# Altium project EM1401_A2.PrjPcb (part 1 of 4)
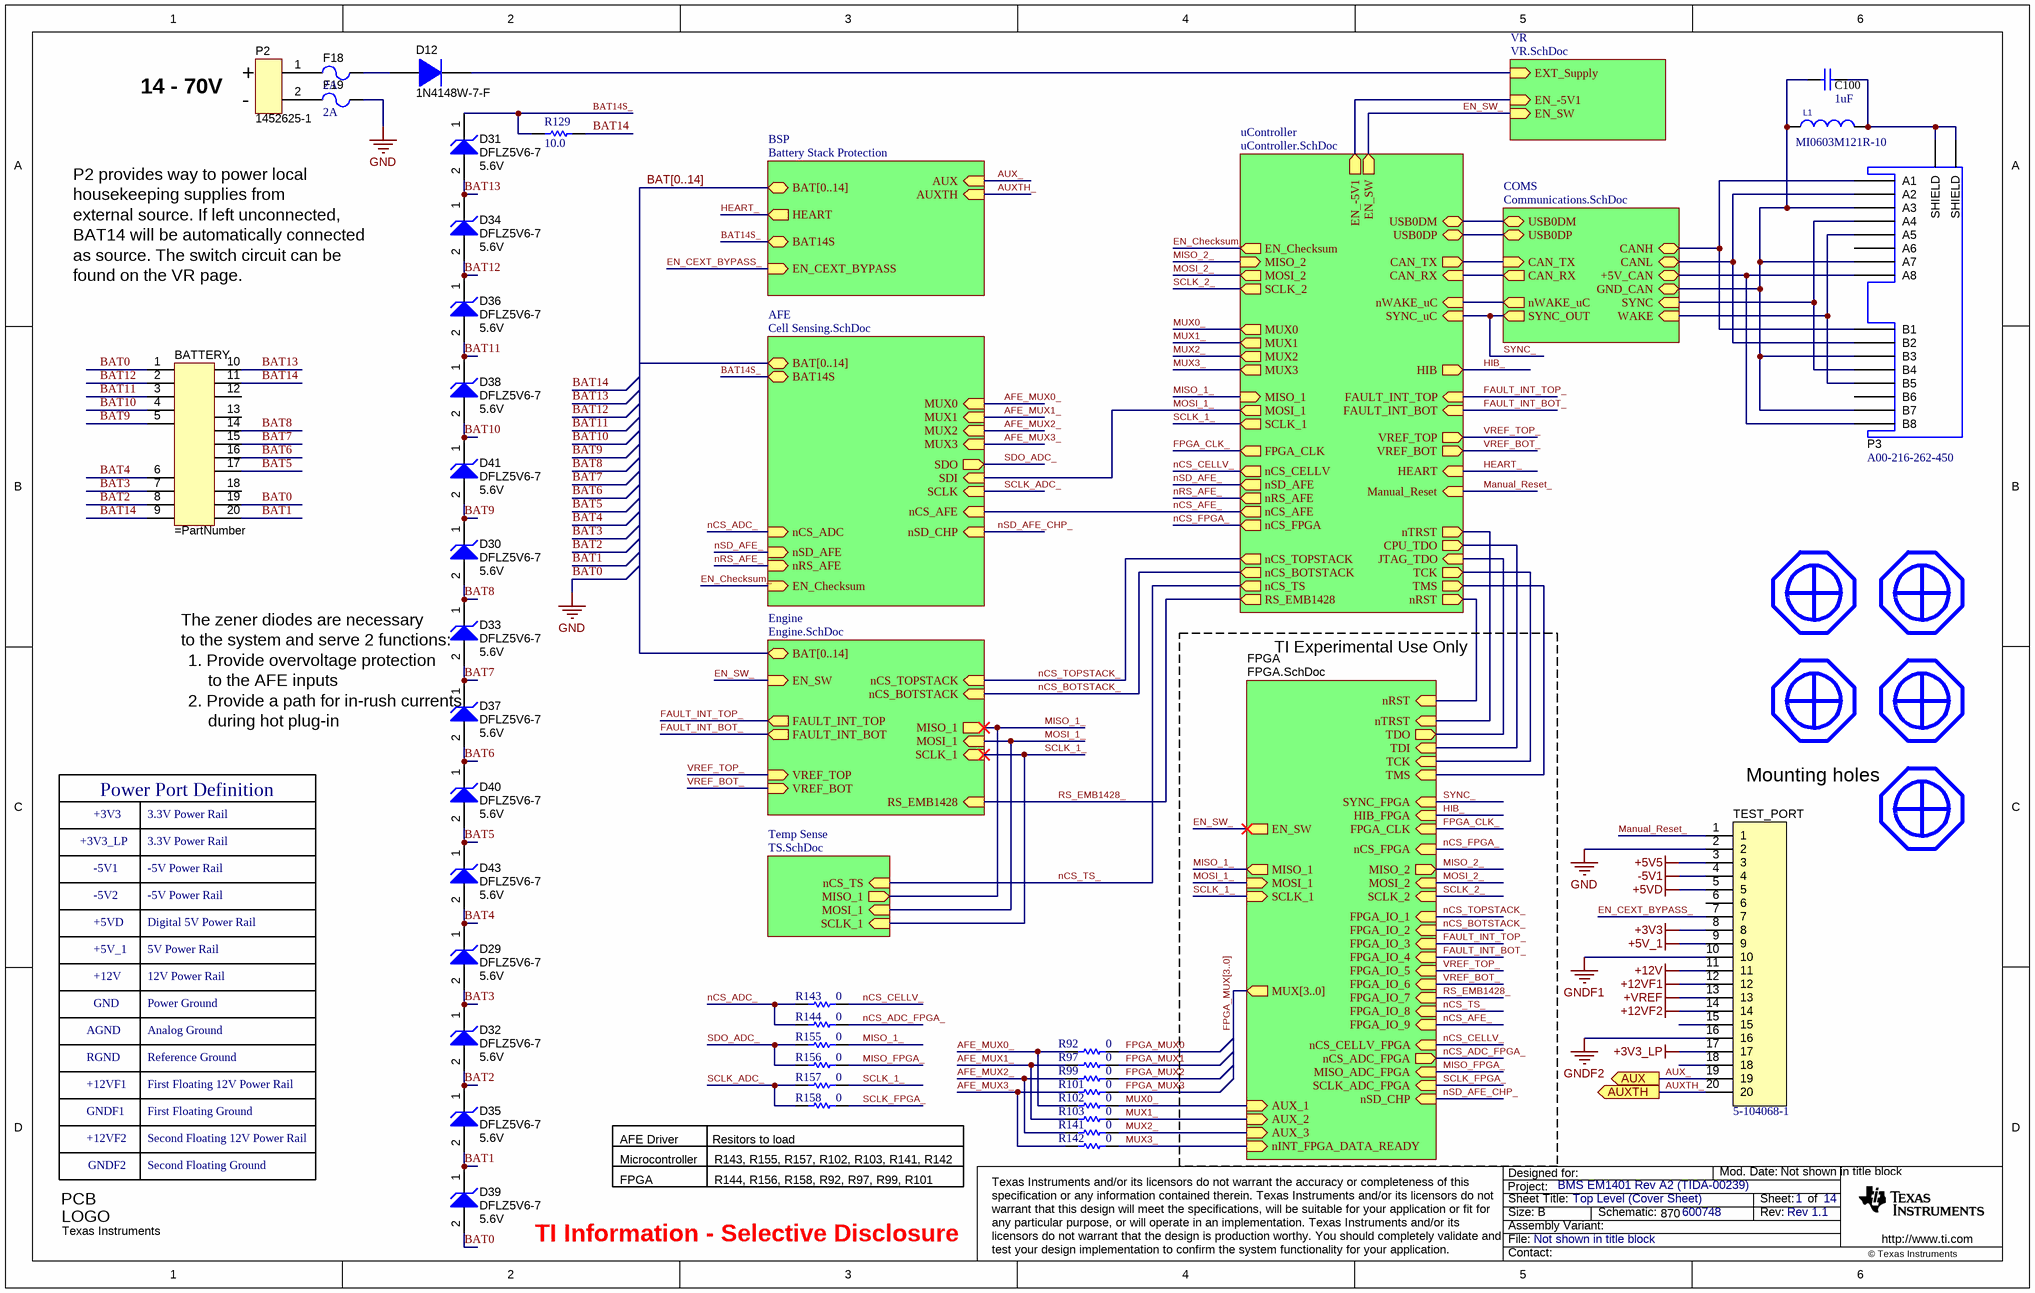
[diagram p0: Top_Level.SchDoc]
SCH_Rev: Rev 1.1; PRJ_Title: BMS EM1401 Rev A2 (TIDA-00239); PRJ_BasePN: 600748; PCB_MinorRev: A2
14 sheets, 751 parts. Net scope: hierarchical (ports join the sheet entries above them; power ports are global).
Board file: EM1401_RevA2.PcbDoc
Sheets:
  Top_Level.SchDoc
    Engine = Engine.SchDoc
      Top Half Stack = TOP Half Stack.SchDoc
        TOP_Converter = TOP_ACB_Converter.SchDoc
      Bottom Half Stack = BOTTOM Half Stack.SchDoc
        BOTTOM_Converter = BOTTOM_ACB_Converter.SchDoc
    VR = VR.SchDoc
    AFE = Cell Sensing.SchDoc
    uController = uController.SchDoc
    COMS = Communications.SchDoc
    BSP = Battery Stack Protection.SchDoc
    Temp Sense = TS.SchDoc
    FPGA = FPGA.SchDoc
  Revision_History.SchDoc

## Sheet Top_Level.SchDoc: Top Level (Cover Sheet)
size B; Date: Not shown in title block; ApprovedBy: Not shown in title block; CheckedBy: Not shown in title block; Author: Not shown in title block; CompanyName: Not shown in title block; DrawnBy: Not shown in title block; Engineer: Not shown in title block; Organization: Not shown in title block; Address1: Not shown in title block; Address2: Not shown in title block; Address3: Not shown in title block; Address4: Not shown in title block; DocumentNumber: 1; Revision: Use project parameter SCH_Rev; SheetNumber: 1; SheetTotal: 14; PageSetup: Record=PageOptions|CenterHorizontal=True|CenterVertical=True|PrintScale=1.09|XCorrection=1.00|YCorrection=1.00|PrintKind=0|BorderSize=5000000|LeftOffset=0|BottomOffset=0|Orientation=2|PaperLength=1000|PaperWidth=1000|Scale=100|PaperSource=15|PrintQuality=600|MediaType=1|DitherType=10|PaperKind=11x17|PrintScaleMode=1

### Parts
BATTERY  (no value)  [175785]
C100  value 1uF  [0805_HV]  (hidden comment: C2012X7R1E105K)
D12  1N4148W-7-F  [SOD-123]
D29  DFLZ5V6-7  value 5.6V  [powerDI123]
D30  DFLZ5V6-7  value 5.6V  [powerDI123]
D31  DFLZ5V6-7  value 5.6V  [powerDI123]
D32  DFLZ5V6-7  value 5.6V  [powerDI123]
D33  DFLZ5V6-7  value 5.6V  [powerDI123]
D34  DFLZ5V6-7  value 5.6V  [powerDI123]
D35  DFLZ5V6-7  value 5.6V  [powerDI123]
D36  DFLZ5V6-7  value 5.6V  [powerDI123]
D37  DFLZ5V6-7  value 5.6V  [powerDI123]
D38  DFLZ5V6-7  value 5.6V  [powerDI123]
D39  DFLZ5V6-7  value 5.6V  [powerDI123]
D40  DFLZ5V6-7  value 5.6V  [powerDI123]
D41  DFLZ5V6-7  value 5.6V  [powerDI123]
D43  DFLZ5V6-7  value 5.6V  [powerDI123]
F18  value 2A  [0459002.UR]  (hidden comment: 0459002.UR)
F19  value 2A  [0459002.UR]  (hidden comment: 0459002.UR)
L1  MI0603M121R-10  [0603]
Logo1  Texas Instruments  [TI_Logo_CopperSolderMask_1p1_x_p275]  (no BOM)
MNT1  Used in BOM report  [4-40 screw]  (value not drawn)
MNT2  Used in BOM report  [4-40 screw]  (value not drawn)
MNT3  Used in BOM report  [4-40 screw]  (value not drawn)
MNT4  Used in BOM report  [4-40 screw]  (value not drawn)
MNT5  Used in BOM report  [4-40 screw]  (value not drawn)
P2  1452625-1  [1452625-1]
P3  A00-216-262-450  [A00-216-262-450]
R92  value 0  [0603L]  (hidden comment: CRCW06030000Z0EA)
R97  value 0  [0603L]  (hidden comment: CRCW06030000Z0EA)
R99  value 0  [0603L]  (hidden comment: CRCW06030000Z0EA)
R101  value 0  [0603L]  (hidden comment: CRCW06030000Z0EA)
R102  value 0  [0603L]  (hidden comment: CRCW06030000Z0EA)
R103  value 0  [0603L]  (hidden comment: CRCW06030000Z0EA)
R129  value 10.0  [0805_HV]  (hidden comment: CRCW080510R0FKEA)
R141  value 0  [0603L]  (hidden comment: CRCW06030000Z0EA)
R142  value 0  [0603L]  (hidden comment: CRCW06030000Z0EA)
R143  value 0  [0603L]  (hidden comment: CRCW06030000Z0EA)
R144  value 0  [0603L]  (hidden comment: CRCW06030000Z0EA)
R155  value 0  [0603L]  (hidden comment: CRCW06030000Z0EA)
R156  value 0  [0603L]  (hidden comment: CRCW06030000Z0EA)
R157  value 0  [0603L]  (hidden comment: CRCW06030000Z0EA)
R158  value 0  [0603L]  (hidden comment: CRCW06030000Z0EA)
TEST_PORT  5-104068-1  [5-104068-1]

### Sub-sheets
AFE = Cell Sensing.SchDoc: BAT[0..14], nCS_AFE (in), MUX0 (in), MUX1 (in), MUX2 (in), MUX3 (in), BAT14S, SDI (in), SCLK (in), nSD_AFE (in), nRS_AFE (in), nCS_ADC (in), EN_Checksum (in), SDO (out), nSD_CHP (in)
BSP = Battery Stack Protection: HEART (out), BAT[0..14], BAT14S, EN_CEXT_BYPASS (in), AUXTH (in), AUX (in)
COMS = Communications.SchDoc: CAN_TX (in), CAN_RX (out), +5V_CAN, CANL, CANH, nWAKE_uC (out), SYNC_OUT (out), SYNC (in), WAKE (in), GND_CAN, USB0DM (bidir), USB0DP (bidir)
Engine = Engine.SchDoc: MOSI_1 (in), MISO_1 (out), BAT[0..14], SCLK_1 (in), nCS_TOPSTACK (in), nCS_BOTSTACK (in), VREF_BOT (in), VREF_TOP (in), FAULT_INT_TOP (out), FAULT_INT_BOT (out), RS_EMB1428 (in), EN_SW (in)
FPGA = FPGA.SchDoc: TDO (out), TDI (in), TCK (in), TMS (in), nTRST (in), nCS_FPGA (in), nRST (in), SYNC_FPGA (in), SCLK_2 (in), MISO_2 (out), MOSI_2 (in), HIB_FPGA (in), FPGA_CLK (in), FPGA_IO_1 (in), FPGA_IO_2 (in), FPGA_IO_3 (in), FPGA_IO_4 (in), FPGA_IO_5 (in), FPGA_IO_6 (in), FPGA_IO_7 (in), FPGA_IO_8 (in), FPGA_IO_9 (in), MUX[3..0] (out), AUX_2 (in), AUX_1 (in), AUX_3 (in), nINT_FPGA_DATA_READY (in), nCS_CELLV_FPGA (in), nCS_ADC_FPGA (out), MISO_ADC_FPGA (in), SCLK_ADC_FPGA (in), SCLK_1 (in), MISO_1 (out), MOSI_1 (in), nSD_CHP (in), EN_SW (out)
Temp Sense = TS.SchDoc: nCS_TS (in), MOSI_1 (in), MISO_1 (out), SCLK_1 (in)
uController = uController.SchDoc: CAN_TX (out), CAN_RX (in), SCLK_1 (out), MOSI_1 (out), MUX0 (out), MUX1 (out), MUX2 (out), MUX3 (out), nSD_AFE (out), nRS_AFE (out), MISO_1 (in), nCS_TOPSTACK (out), nCS_BOTSTACK (out), nCS_AFE (out), nCS_TS (out), EN_-5V1 (out), EN_SW (out), VREF_TOP (out), VREF_BOT (out), nCS_CELLV (out), HEART (in), RS_EMB1428 (out), nWAKE_uC (in), SCLK_2 (out), MISO_2 (in), MOSI_2 (out), EN_Checksum (out), SYNC_uC (in), USB0DM (bidir), USB0DP (bidir), Manual_Reset (in), JTAG_TDO (in), TCK (out), TMS (out), nRST (out), nTRST (out), FAULT_INT_BOT (in), FAULT_INT_TOP (in), HIB (out), FPGA_CLK (out), nCS_FPGA (out), CPU_TDO (out)
VR = VR.SchDoc: EN_-5V1 (in), EN_SW (in), EXT_Supply (in)

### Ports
AUX (out), AUXTH (out)

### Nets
+3V3: TEST_PORT.8
+3V3_LP: TEST_PORT.17
+5V5: TEST_PORT.3
+5V_1: TEST_PORT.9
+5V_CAN: P3.A8 P3.B8 ; sheet COMS/+5V_CAN
+5VD: TEST_PORT.5
+12V: TEST_PORT.11
+12VF1: TEST_PORT.12
+12VF2: TEST_PORT.14
+VREF: TEST_PORT.13
-5V1: TEST_PORT.4
BAT0: BATTERY.1 BATTERY.19 D39.2(A) F19.1 TEST_PORT.2  [also labelled GND]
CAN_GND: C100.1 L1.1 P3.A3 P3.A7 P3.B3 P3.B7 ; sheet COMS/GND_CAN
GNDF1: TEST_PORT.10
GNDF2: TEST_PORT.16
AFE_MUX0_: R92.2 R102.2 ; sheet AFE/MUX0
AFE_MUX1_: R97.2 R103.2 ; sheet AFE/MUX1
AFE_MUX2_: R99.2 R141.2 ; sheet AFE/MUX2
AFE_MUX3_: R101.2 R142.2 ; sheet AFE/MUX3
AUX_: TEST_PORT.19 ; port AUX, sheet BSP/AUX
AUXTH_: TEST_PORT.20 ; port AUXTH, sheet BSP/AUXTH
BAT1: BATTERY.20 D35.2(A) D39.1(K)
BAT2: BATTERY.8 D32.2(A) D35.1(K)
BAT3: BATTERY.7 D29.2(A) D32.1(K)
BAT4: BATTERY.6 D29.1(K) D43.2(A)
BAT5: BATTERY.17 D40.2(A) D43.1(K)
BAT6: BATTERY.16 D37.2(A) D40.1(K)
BAT7: BATTERY.15 D33.2(A) D37.1(K)
BAT8: BATTERY.14 D30.2(A) D33.1(K)
BAT9: BATTERY.5 D30.1(K) D41.2(A)
BAT10: BATTERY.4 D38.2(A) D41.1(K)
BAT11: BATTERY.3 D36.2(A) D38.1(K)
BAT12: BATTERY.2 D34.2(A) D36.1(K)
BAT13: BATTERY.10 D31.2(A) D34.1(K)
BAT14: BATTERY.9 BATTERY.11 R129.1
BAT14S_: D31.1(K) R129.2 ; sheet AFE/BAT14S, sheet BSP/BAT14S
EN_CEXT_BYPASS_: TEST_PORT.7 ; sheet BSP/EN_CEXT_BYPASS
EN_Checksum_: sheet AFE/EN_Checksum, sheet uController/EN_Checksum
EN_SW_: sheet Engine/EN_SW, sheet VR/EN_SW, sheet uController/EN_SW, sheet FPGA/EN_SW
FAULT_INT_BOT_: sheet Engine/FAULT_INT_BOT, sheet uController/FAULT_INT_BOT, sheet FPGA/FPGA_IO_4
FAULT_INT_TOP_: sheet Engine/FAULT_INT_TOP, sheet uController/FAULT_INT_TOP, sheet FPGA/FPGA_IO_3
FPGA_CLK_: sheet uController/FPGA_CLK, sheet FPGA/FPGA_CLK
FPGA_MUX0: R92.1
FPGA_MUX1: R97.1
FPGA_MUX2: R99.1
FPGA_MUX3: R101.1
HEART_: sheet uController/HEART, sheet BSP/HEART
HIB_: sheet uController/HIB, sheet FPGA/HIB_FPGA
JTAG_TDO: sheet uController/JTAG_TDO, sheet FPGA/TDO
JTCK/SWCLK: sheet uController/TCK, sheet FPGA/TCK
JTDO/TRACESWO: sheet uController/CPU_TDO, sheet FPGA/TDI
JTMS/SWDIO: sheet uController/TMS, sheet FPGA/TMS
Manual_Reset_: TEST_PORT.1 ; sheet uController/Manual_Reset
MISO_1_: R155.2 ; sheet Engine/MISO_1, sheet uController/MISO_1, sheet Temp Sense/MISO_1, sheet FPGA/MISO_1
MISO_2_: sheet uController/MISO_2, sheet FPGA/MISO_2
MISO_FPGA_: R156.2 ; sheet FPGA/MISO_ADC_FPGA
MOSI_1_: sheet Engine/MOSI_1, sheet AFE/SDI, sheet uController/MOSI_1, sheet Temp Sense/MOSI_1, sheet FPGA/MOSI_1
MOSI_2_: sheet uController/MOSI_2, sheet FPGA/MOSI_2
MUX0_: R102.1 ; sheet uController/MUX0, sheet FPGA/AUX_1
MUX1_: R103.1 ; sheet uController/MUX1, sheet FPGA/AUX_2
MUX2_: R141.1 ; sheet uController/MUX2, sheet FPGA/AUX_3
MUX3_: R142.1 ; sheet uController/MUX3, sheet FPGA/nINT_FPGA_DATA_READY
nCS_ADC_: R143.2 R144.2 ; sheet AFE/nCS_ADC
nCS_ADC_FPGA_: R144.1 ; sheet FPGA/nCS_ADC_FPGA
nCS_AFE_: sheet AFE/nCS_AFE, sheet uController/nCS_AFE, sheet FPGA/FPGA_IO_9
nCS_BOTSTACK_: sheet Engine/nCS_BOTSTACK, sheet uController/nCS_BOTSTACK, sheet FPGA/FPGA_IO_2
nCS_CELLV_: R143.1 ; sheet uController/nCS_CELLV, sheet FPGA/nCS_CELLV_FPGA
nCS_FPGA_: sheet uController/nCS_FPGA, sheet FPGA/nCS_FPGA
nCS_TOPSTACK_: sheet Engine/nCS_TOPSTACK, sheet uController/nCS_TOPSTACK, sheet FPGA/FPGA_IO_1
nCS_TS_: sheet uController/nCS_TS, sheet Temp Sense/nCS_TS, sheet FPGA/FPGA_IO_8
nRS_AFE_: sheet AFE/nRS_AFE, sheet uController/nRS_AFE
nRST: sheet uController/nRST, sheet FPGA/nRST
nSD_AFE_: sheet AFE/nSD_AFE, sheet uController/nSD_AFE
nSD_AFE_CHP_: sheet AFE/nSD_CHP, sheet FPGA/nSD_CHP
RS_EMB1428_: sheet Engine/RS_EMB1428, sheet uController/RS_EMB1428, sheet FPGA/FPGA_IO_7
SCLK_1_: R157.2 ; sheet Engine/SCLK_1, sheet uController/SCLK_1, sheet Temp Sense/SCLK_1, sheet FPGA/SCLK_1
SCLK_2_: sheet uController/SCLK_2, sheet FPGA/SCLK_2
SCLK_ADC_: R157.1 R158.1 ; sheet AFE/SCLK
SCLK_FPGA_: R158.2 ; sheet FPGA/SCLK_ADC_FPGA
SDO_ADC_: R155.1 R156.1 ; sheet AFE/SDO
SYNC_: sheet uController/SYNC_uC, sheet COMS/SYNC_OUT, sheet FPGA/SYNC_FPGA
VREF_BOT_: sheet Engine/VREF_BOT, sheet uController/VREF_BOT, sheet FPGA/FPGA_IO_6
VREF_TOP_: sheet Engine/VREF_TOP, sheet uController/VREF_TOP, sheet FPGA/FPGA_IO_5
NetC57_2: P3.A2 P3.B2 ; sheet COMS/CANL
NetC59_1: P3.A1 P3.B1 ; sheet COMS/CANH
NetC100_2: C100.2 L1.2 P3.10(SHIELD)
NetD4_1: sheet uController/USB0DM, sheet COMS/USB0DM
NetD9_1: sheet uController/USB0DP, sheet COMS/USB0DP
NetD11_2: D12.1(K) ; sheet VR/EXT_Supply
NetD12_2: D12.2(A) F18.1
NetF18_2: F18.2 P2.1
NetF19_2: F19.2 P2.2
NetJ7_3: sheet uController/nTRST, sheet FPGA/nTRST
NetP3_A4: P3.A4 P3.B4 ; sheet COMS/SYNC
NetP3_A5: P3.A5 P3.B5 ; sheet COMS/WAKE
NetQ45_3: sheet uController/nWAKE_uC, sheet COMS/nWAKE_uC
NetR27_1: sheet uController/CAN_TX, sheet COMS/CAN_TX
NetR38_1: sheet uController/CAN_RX, sheet COMS/CAN_RX
NetR94_2: sheet VR/EN_-5V1, sheet uController/EN_-5V1

Not connected (* = marked no-connect by the designer): BATTERY 12 13 18; P3 A6 B6; TEST_PORT 6 15 18

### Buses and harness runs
bus BAT[0..14] = sheet AFE/BAT[0..14] = sheet BSP/BAT[0..14] = sheet Engine/BAT[0..14]
bus FPGA_MUX[3..0] = sheet FPGA/MUX[3..0]

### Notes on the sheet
- 14 - 70V
- (near P2) +
- (near P2) -
- P2 provides way to power local
- housekeeping supplies from
- external source. If left unconnected,
- BAT14 will be automatically connected
- as source. The switch circuit can be
- found on the VR page.
- (near D33) The zener diodes are necessary
- (near D33) to the system and serve 2 functions:
- TI Experimental Use Only
- (near D33) 1. Provide overvoltage protection
- (near D37) 2. Provide a path for in-rush currents
- to the AFE inputs
- during hot plug-in
- Mounting holes
- +3V3
- Power Port Definition
- 3.3V Power Rail
- +3V3_LP
- -5V2
- -5V1
- -5V Power Rail
- +5V_1
- +5VD
- 5V Power Rail
- Digital 5V Power Rail
- AGND
- +12V
- GND
- 12V Power Rail
- Power Ground
- Analog Ground
- +12VF1
- RGND
- First Floating 12V Power Rail
- Reference Ground
- +12VF2
- GNDF1
- (near Logo1) GNDF2
- Second Floating 12V Power Rail
- First Floating Ground
- Second Floating Ground
- AFE Driver
- Microcontroller
- FPGA
- R143, R155, R157, R102, R103, R141, R142
- R144, R156, R158, R92, R97, R99, R101
- (near R158) Resitors to load
- TI Information - Selective Disclosure

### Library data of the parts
BATTERY = 175785-1: .070 SERIES MULTI-LOCK I/O CONN. 20Pos. PCB 90 Horiz; Manufacturer: Tyco; CompType: Connector
C100 = C2012X7R1E105K: CAP, CERM, 1uF, 25V, +/-10%, X7R, 0805; Manufacturer: TDK; Cap_Case: 0805; ESR_Ohm: 0.0075; Polarized: N; TaMax_C: 125; TaMin_C: -55; Tolerance_%: 10; VDC_V: 25; Cap_F: 0.000001; CompType: Capacitor; Value1: 0.0075 ohm; U/M: EA; ValueDisplayed: 1µF
D12 = 1N4148W-7-F: Diode, Ultrafast, 100V, 0.15A, SOD-123; Manufacturer: Diodes Inc.; U/M: EA; Vf_V: 1.25; Io_A: 0.15; Vr_V: 100; TJmax_C: 150; Value: 1.25V
D29-D41 D43 = DFLZ5V6-7: Diode, Zener, 5.6V, 1W, PowerDI123; Manufacturer: Diodes Inc.; Power_W: 1; U/M: EA; Vz: 5.6; RJA_CperW: 110
F18 F19 = 0459002.UR: FUSE 2A 125V  FAST ACTING; Manufacturer: LittleFuse Inc; SymbolVersion: use current date i.e. 2008-05-20; SymbolCreator: Use LDAP id
L1 = Ferrite Bead: Ferrite bead, 120mOhm, 2A, 0603; Manufacturer: Steward
Logo1 = TI_Logo: Texas Instrument Corporate Signature; SymbolCreator: codlsc
MNT1-MNT5 = 4-40 screw mount: 4-40 screw for mounting hardware; SymbolVersion: use current date i.e. 2008-05-20; SymbolCreator: Use LDAP id
P2 = 1452625-1: Tyco .64 Series GET Connector 2 position
P3 = A00-216-262-450: RJ45 2X1 8 Position Jack; Manufacturer: EDAC; CompType: Connector
R92 R97 R99 R101-R103 R141-R144 R155-R158 = CRCW06030000Z0EA: RES, 0 ohm, 5%, 0.1W, 0603; Manufacturer: Vishay-Dale; CompType: Resistor; Tolerance_%: 5; VDC_V: 75; Power_W: 0.1; Value_Code: 0000; EIA_Code: E24; TempCo: 200 ppm/C; U/M: EA
R129 = CRCW080510R0FKEA: RES, 10.0 ohm, 1%, 0.125W, 0805; Manufacturer: Vishay-Dale; CompType: Resistor; Tolerance_%: 1; VDC_V: 150; Power_W: 0.125; Res_Ohm: 10; Value_Code: 10R0; EIA_Code: E96; TempCo: 100 ppm/C; U/M: EA
TEST_PORT = 5-104068-1: 20Pin AMP Connector VERT HEADER; Manufacturer: AMP Incorporated

## Sheet Engine.SchDoc: Engine (Cell balance converters)
size B; Date: Not shown in title block; ApprovedBy: Not shown in title block; CheckedBy: Not shown in title block; Author: Not shown in title block; CompanyName: Not shown in title block; DrawnBy: Not shown in title block; Engineer: Not shown in title block; Organization: Not shown in title block; Address1: Not shown in title block; Address2: Not shown in title block; Address3: Not shown in title block; Address4: Not shown in title block; DocumentNumber: 4; Revision: Use project parameter SCH_Rev; SheetNumber: 5; SheetTotal: 14; PageSetup: Record=PageOptions|CenterHorizontal=True|CenterVertical=True|PrintScale=0.70|XCorrection=1.00|YCorrection=1.00|PrintKind=0|BorderSize=5000000|LeftOffset=0|BottomOffset=0|Orientation=2|PaperLength=1000|PaperWidth=1000|Scale=100|PaperSource=15|PrintQuality=600|MediaType=1|DitherType=10|PaperKind=Letter|PrintScaleMode=1
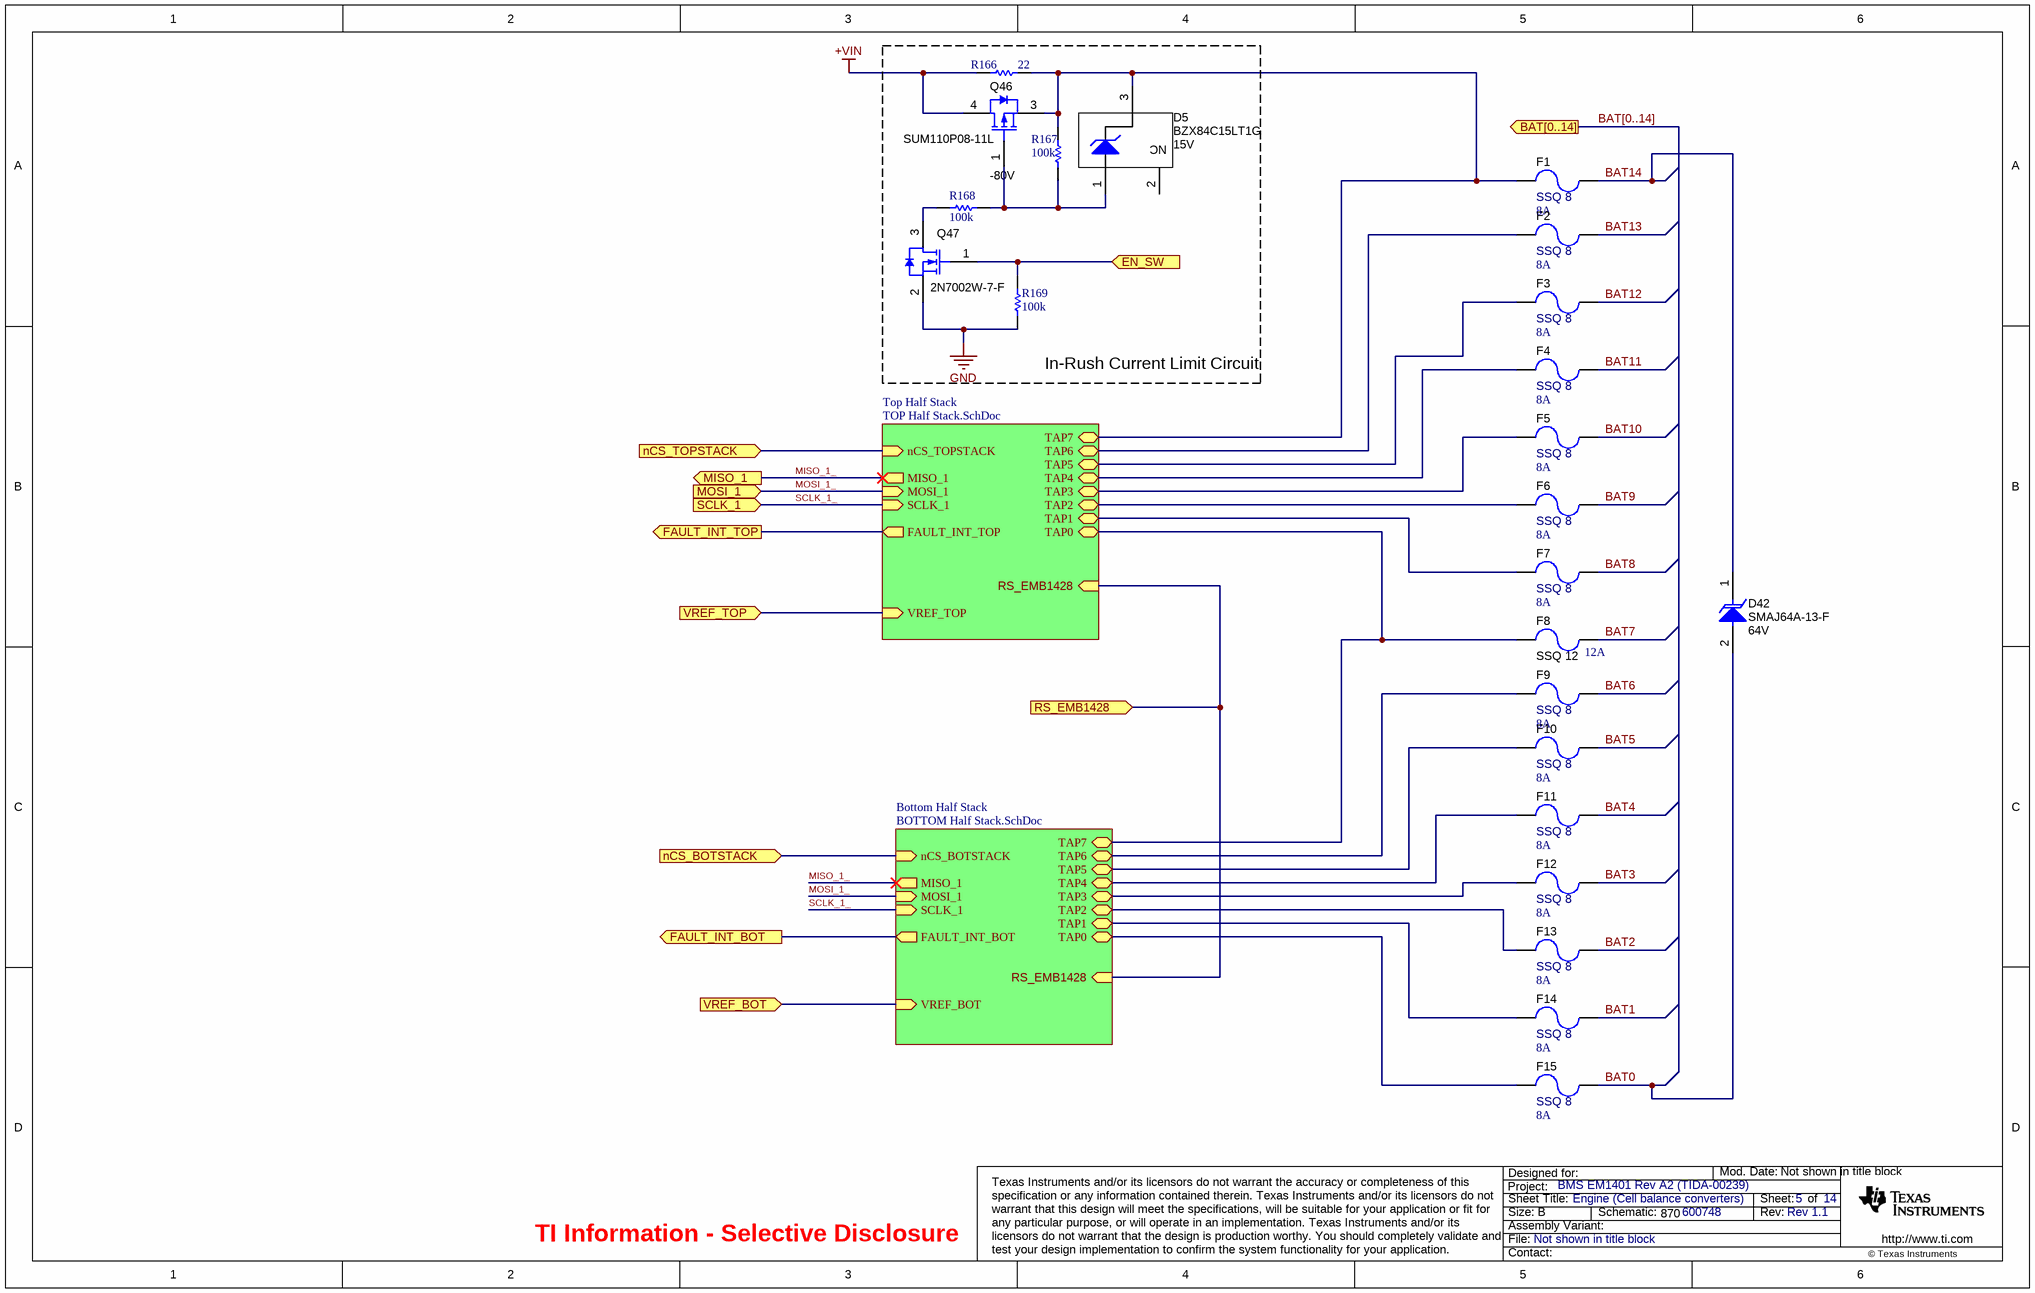
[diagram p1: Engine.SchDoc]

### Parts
D5  BZX84C15LT1G  value 15V  [SOT-23]
D42  SMAJ64A-13-F  value 64V  [SMA]
F1  SSQ 8  value 8A  [SSQ8A]
F2  SSQ 8  value 8A  [SSQ8A]
F3  SSQ 8  value 8A  [SSQ8A]
F4  SSQ 8  value 8A  [SSQ8A]
F5  SSQ 8  value 8A  [SSQ8A]
F6  SSQ 8  value 8A  [SSQ8A]
F7  SSQ 8  value 8A  [SSQ8A]
F8  SSQ 12  value 12A  [SSQ8A]
F9  SSQ 8  value 8A  [SSQ8A]
F10  SSQ 8  value 8A  [SSQ8A]
F11  SSQ 8  value 8A  [SSQ8A]
F12  SSQ 8  value 8A  [SSQ8A]
F13  SSQ 8  value 8A  [SSQ8A]
F14  SSQ 8  value 8A  [SSQ8A]
F15  SSQ 8  value 8A  [SSQ8A]
Q46  SUM110P08-11L  value -80V  [DDPAK]
Q47  2N7002W-7-F  [SOT-323]
R166  value 22  [2512M]  (hidden comment: ERJ-1TYJ220U)
R167  value 100k  [0603L]  (hidden comment: CRCW0603100KFKEA)
R168  value 100k  [0603L]  (hidden comment: CRCW0603100KFKEA)
R169  value 100k  [0603L]  (hidden comment: CRCW0603100KFKEA)

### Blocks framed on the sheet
In-Rush Current Limit Circuit: D5 Q46 Q47 R166-R169

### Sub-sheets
Bottom Half Stack = BOTTOM Half Stack.SchDoc: TAP5, TAP4, TAP3, TAP2, TAP1, TAP0, TAP6, TAP7, nCS_BOTSTACK (in), MISO_1 (out), MOSI_1 (in), SCLK_1 (in), FAULT_INT_BOT (out), VREF_BOT (in), RS_EMB1428 (in)
Top Half Stack = TOP Half Stack.SchDoc: TAP5, TAP4, TAP3, TAP2, TAP1, TAP0, TAP6, TAP7, nCS_TOPSTACK (in), MISO_1 (out), MOSI_1 (in), SCLK_1 (in), FAULT_INT_TOP (out), VREF_TOP (in), RS_EMB1428 (in)

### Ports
BAT[0..14], EN_SW (in), FAULT_INT_BOT (out), FAULT_INT_TOP (out), MISO_1 (out), MOSI_1 (in), nCS_BOTSTACK (in), nCS_TOPSTACK (in), RS_EMB1428 (in), SCLK_1 (in), VREF_BOT (in), VREF_TOP (in)

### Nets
+VIN: Q46.4(D) R166.1  [project net TIN_P_BOT]
BAT0: D42.2(A) F15.2 Q47.2(S) R169.2  [also labelled GND]
BAT1: F14.2
BAT2: F13.2
BAT3: F12.2
BAT4: F11.2
BAT5: F10.2
BAT6: F9.2
BAT7: F8.1
BAT8: F7.2
BAT9: F6.1
BAT10: F5.2
BAT11: F4.2
BAT12: F3.2
BAT13: F2.2
BAT14: D42.1(K) F1.2
EN_SW_: Q47.1(G) R169.1 ; port EN_SW
FAULT_INT_BOT_: port FAULT_INT_BOT, sheet Bottom Half Stack/FAULT_INT_BOT
FAULT_INT_TOP_: port FAULT_INT_TOP, sheet Top Half Stack/FAULT_INT_TOP
MISO_1_: port MISO_1, sheet Top Half Stack/MISO_1, sheet Bottom Half Stack/MISO_1
MOSI_1_: port MOSI_1, sheet Top Half Stack/MOSI_1, sheet Bottom Half Stack/MOSI_1
nCS_BOTSTACK_: port nCS_BOTSTACK, sheet Bottom Half Stack/nCS_BOTSTACK
nCS_TOPSTACK_: port nCS_TOPSTACK, sheet Top Half Stack/nCS_TOPSTACK
RS_EMB1428_: port RS_EMB1428, sheet Top Half Stack/RS_EMB1428, sheet Bottom Half Stack/RS_EMB1428
SCLK_1_: port SCLK_1, sheet Top Half Stack/SCLK_1, sheet Bottom Half Stack/SCLK_1
VREF_BOT_: port VREF_BOT, sheet Bottom Half Stack/VREF_BOT
VREF_TOP_: port VREF_TOP, sheet Top Half Stack/VREF_TOP
NetD5_1: D5.1(A) Q46.1(G) R167.1 R168.1
NetD5_3: D5.3(K) F1.1 Q46.3(S) R166.2 R167.2 ; sheet Top Half Stack/TAP7
NetF2_1: F2.1 ; sheet Top Half Stack/TAP6
NetF3_1: F3.1 ; sheet Top Half Stack/TAP5
NetF4_1: F4.1 ; sheet Top Half Stack/TAP4
NetF5_1: F5.1 ; sheet Top Half Stack/TAP3
NetF6_2: F6.2 ; sheet Top Half Stack/TAP2
NetF7_1: F7.1 ; sheet Top Half Stack/TAP1
NetF8_2: F8.2 ; sheet Top Half Stack/TAP0, sheet Bottom Half Stack/TAP7
NetF9_1: F9.1 ; sheet Bottom Half Stack/TAP6
NetF10_1: F10.1 ; sheet Bottom Half Stack/TAP5
NetF11_1: F11.1 ; sheet Bottom Half Stack/TAP4
NetF12_1: F12.1 ; sheet Bottom Half Stack/TAP3
NetF13_1: F13.1 ; sheet Bottom Half Stack/TAP2
NetF14_1: F14.1 ; sheet Bottom Half Stack/TAP1
NetF15_1: F15.1 ; sheet Bottom Half Stack/TAP0
NetQ47_3: Q47.3(D) R168.2

Not connected (* = marked no-connect by the designer): D5 2(NC)

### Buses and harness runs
bus BAT[0..14] = port BAT[0..14]

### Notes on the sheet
- TI Information - Selective Disclosure

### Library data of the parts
D5 = BZX84C15LT1G: Diode, Zener, 15V, 225mW, SOT-23; Manufacturer: ON Semiconductor; U/M: EA; Power_W: 0.225; Vz: 15; Value1: 0.225W; RJA_CperW: 556
D42 = SMBJ64A-13-F: Diode, TVS, Uni, 64V, 400W, SMB; Manufacturer: Diodes Inc.; U/M: EA; Power_W: 5; Vr_V: 64; Value1: 5W
F1-F7 F9-F15 = SSQ 8: FUSE 8A 125V 6125 FAST SSQ; Manufacturer: Bel Fuse Inc
F8 = SSQ 12: FUSE 12A 125V 6125 FAST SSQ; Manufacturer: Bel Fuse Inc
Q46 = SUM110P08-11L: MOSFET, P-CH, -80V, -23.5A, DDPAK; Manufacturer: Vishay-Siliconix; ChType: P; VdsMax_V: -80; Value1: 0.012 ohm; Rdson45_Ohm: 0.012; Value2: 85 nC; QgTyp_nC: 85; Vgs_V: -20; IdsMax_A: -23.5
Q47 = 2N7002W-7-F: MOSFET N-CH 60V 115MA SOT323; Manufacturer: Vishay-Siliconix; ChType: N; VdsMax_V: 60; Value1: 1.8 ohm; Rdson45_Ohm: 1.8; Value2: 0.4 nC; QgTyp_nC: 0.4; Vgs_V: 20; IdsMax_A: 0.24
R166 = ERJ-1TYJ220U: 22 Ohm 1%, 1W; Manufacturer: Panasonic; CompType: Resistor; Tolerance_%: 1; Res_Ohm: 100; Value_Code: R020; EIA_Code: ERJ
R167-R169 = CRCW0603100kFKEA: RES, 100k ohm, 1%, 0.1W, 0603; Manufacturer: Vishay-Dale; CompType: Resistor; Tolerance_%: 1; VDC_V: 75; Power_W: 0.1; Res_Ohm: 100000; EIA_Code: E96; TempCo: 100 ppm/C; U/M: EA

## Sheet TOP Half Stack.SchDoc: Top Half Stack
size B; Date: Not shown in title block; ApprovedBy: Not shown in title block; CheckedBy: Not shown in title block; Author: Not shown in title block; CompanyName: Not shown in title block; DrawnBy: Not shown in title block; Engineer: Not shown in title block; Organization: Not shown in title block; Address1: Not shown in title block; Address2: Not shown in title block; Address3: Not shown in title block; Address4: Not shown in title block; DocumentNumber: 7; Revision: Use project parameter SCH_Rev; SheetNumber: 8; SheetTotal: 14; PageSetup: Record=PageOptions|CenterHorizontal=True|CenterVertical=True|PrintScale=1.09|XCorrection=1.00|YCorrection=1.00|PrintKind=0|BorderSize=5000000|LeftOffset=0|BottomOffset=0|Orientation=2|PaperLength=1000|PaperWidth=1000|Scale=100|PaperSource=15|PrintQuality=600|MediaType=1|DitherType=10|PaperKind=11x17|PrintScaleMode=1
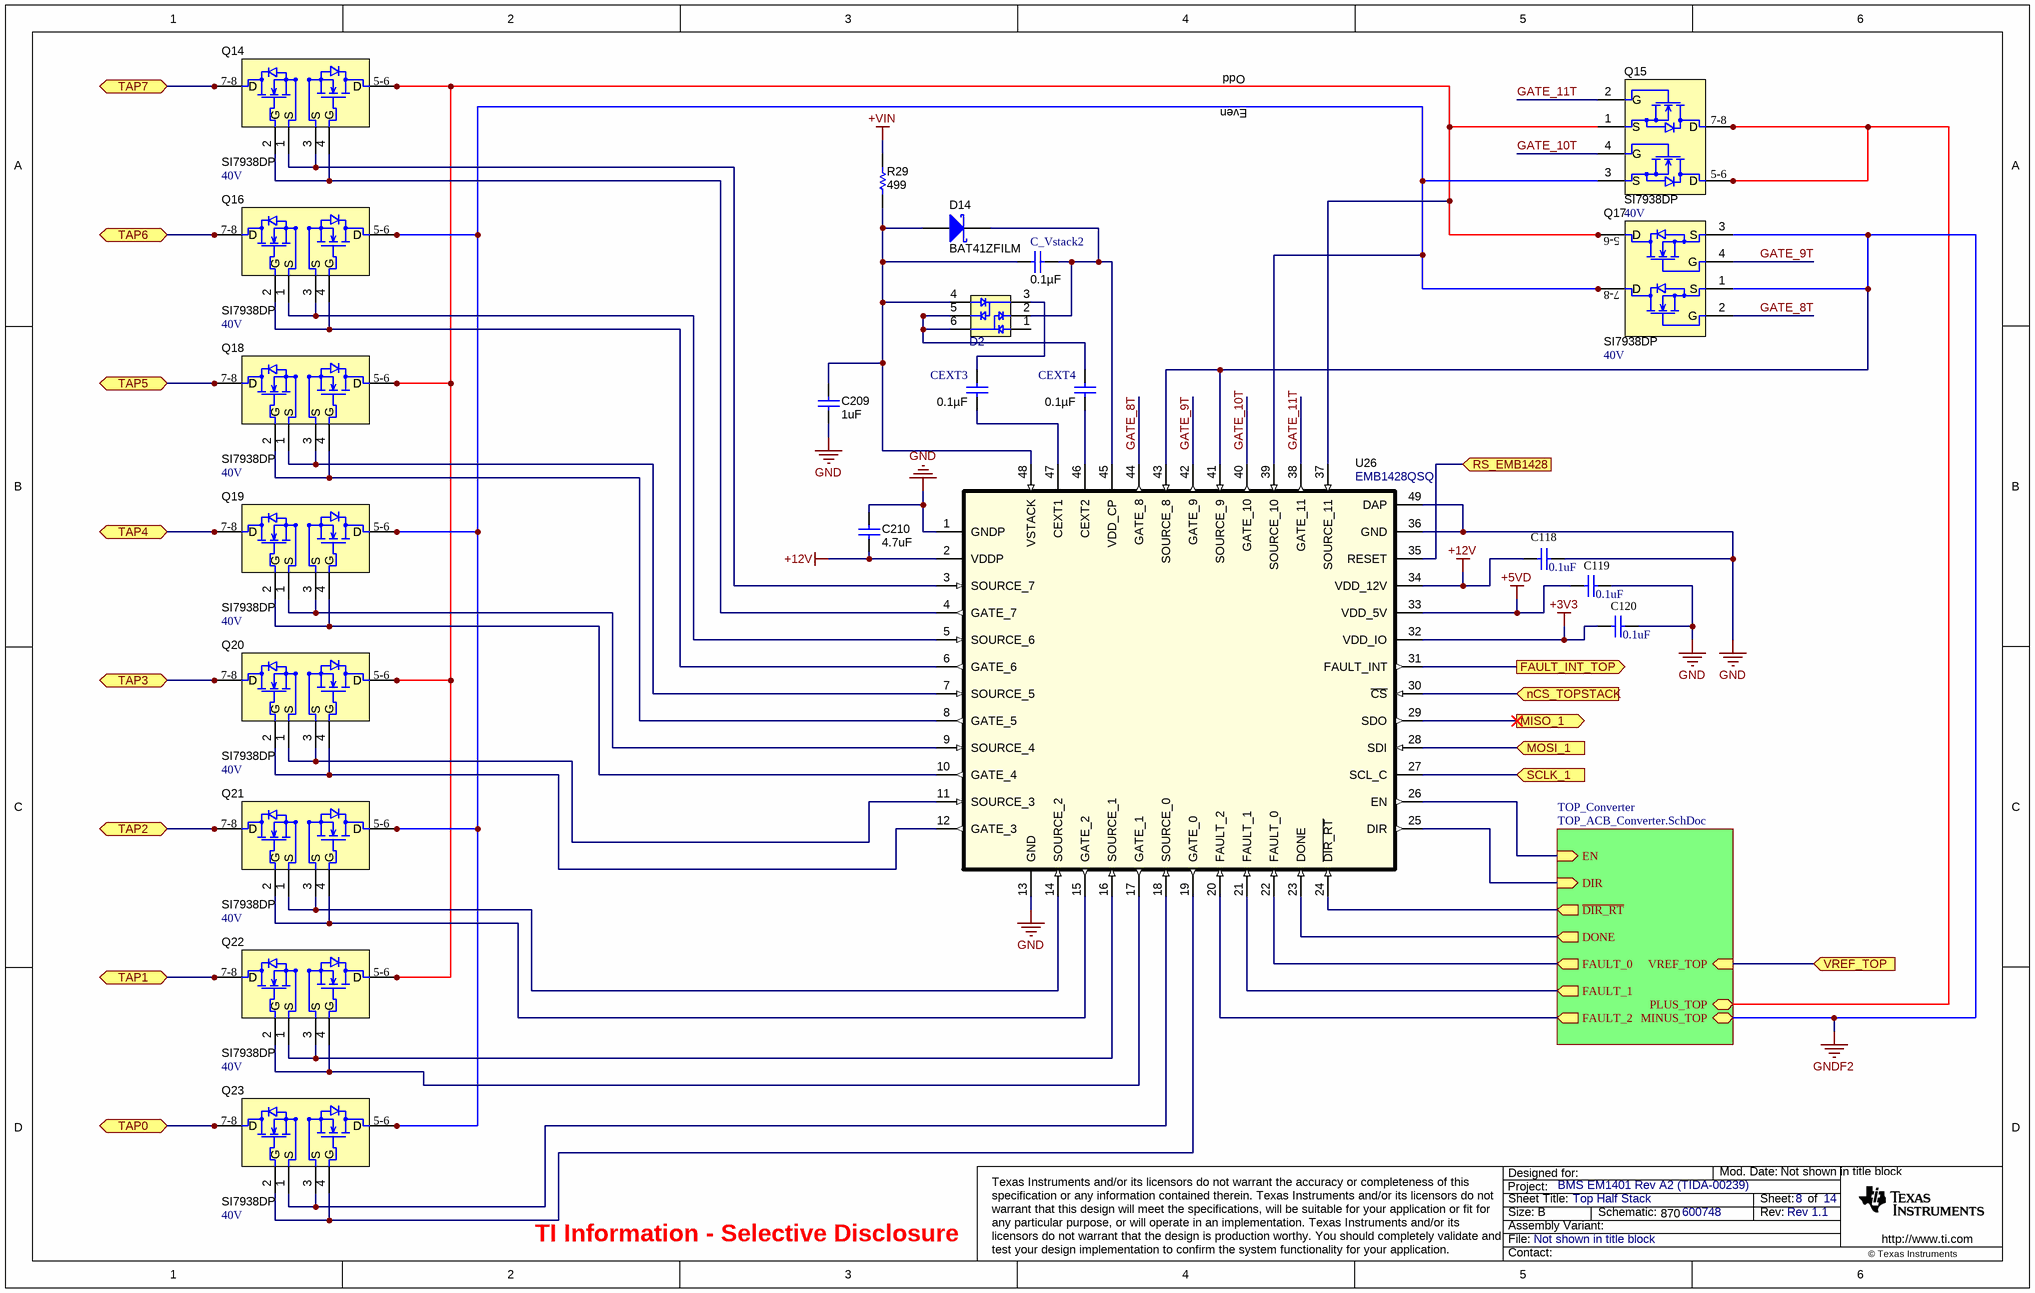
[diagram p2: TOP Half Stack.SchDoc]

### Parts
C118  value 0.1uF  [0603L]  (hidden comment: C1608X7R1C104K)
C119  value 0.1uF  [0603L]  (hidden comment: C1608X7R1C104K)
C120  value 0.1uF  [0603L]  (hidden comment: C1608X7R1C104K)
C209  value 1uF  [1206L]  (hidden comment: C3216X7R2A105M)
C210  value 4.7uF  [0805_HV]  (hidden comment: EMK212BJ475KG-T)
C_Vstack2  ValueDisplayed: 0.1µF  [0805_HV]  (hidden comment: HMK212B7104KG-T)
CEXT3  ValueDisplayed: 0.1µF  [0805_HV]  (hidden comment: HMK212B7104KG-T)
CEXT4  ValueDisplayed: 0.1µF  [0805_HV]  (hidden comment: HMK212B7104KG-T)
D2  BAV99S  [SOT-363]  (value not drawn)
D14  BAT41ZFILM  [SOD-123]
Q14  SI7938DP  Value2: 40V  [POWERPAK SO-8 -Dual]
Q15  SI7938DP  value 40V  [POWERPAK SO-8 -Dual]
Q16  SI7938DP  Value2: 40V  [POWERPAK SO-8 -Dual]
Q17  SI7938DP  value 40V  [POWERPAK SO-8 -Dual]
Q18  SI7938DP  Value2: 40V  [POWERPAK SO-8 -Dual]
Q19  SI7938DP  Value2: 40V  [POWERPAK SO-8 -Dual]
Q20  SI7938DP  Value2: 40V  [POWERPAK SO-8 -Dual]
Q21  SI7938DP  Value2: 40V  [POWERPAK SO-8 -Dual]
Q22  SI7938DP  Value2: 40V  [POWERPAK SO-8 -Dual]
Q23  SI7938DP  Value2: 40V  [POWERPAK SO-8 -Dual]
R29  value 499  [0603L]  (hidden comment: CRCW0603499RFKEA)
U26  EMB1428QSQ  [sqa48a]

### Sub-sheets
TOP_Converter = TOP_ACB_Converter.SchDoc: FAULT_2 (out), FAULT_1 (out), FAULT_0 (out), DIR (in), ~{DIR_RT} (out), DONE (out), EN (in), MINUS_TOP (bidir), PLUS_TOP (bidir), VREF_TOP (in)

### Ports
FAULT_INT_TOP (out), MISO_1 (out), MOSI_1 (in), nCS_TOPSTACK (in), RS_EMB1428 (in), SCLK_1 (in), TAP0 (see 1[4C]), TAP1 (see 1[4C]), TAP2 (see 1[4B]), TAP3 (see 1[4B]), TAP4 (see 1[4B]), TAP5 (see 1[4B]), TAP6 (see 1[4B]), TAP7 (see 1[4B]), VREF_TOP (in)

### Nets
+3V3: C120.2 U26.32(VDD_IO)
+5VD: C119.2 U26.33(VDD_5V)
+12V: C118.2 C210.2 U26.2(VDDP) U26.34(VDD_12V)
+VIN: R29.2  [project net TIN_P_BOT]
GND: C118.1 C119.1 C120.1 C209.1 C210.1 U26.1(GNDP) U26.13(GND) U26.36(GND) U26.49(DAP)  [project net BAT0]
GNDF2: Q17.1(S) Q17.3(S) U26.41(SOURCE_9) U26.43(SOURCE_8) ; sheet TOP_Converter/MINUS_TOP
DIR_RT_TOP: U26.24(~{DIR_RT}) ; sheet TOP_Converter/~{DIR_RT}
DIR_TOP: U26.25(DIR) ; sheet TOP_Converter/DIR
DONE_TOP: U26.23(DONE) ; sheet TOP_Converter/DONE
EN_TOP: U26.26(EN) ; sheet TOP_Converter/EN
FAULT_INT_TOP_: U26.31(FAULT_INT) ; port FAULT_INT_TOP
GATE_8T: Q17.2(G) U26.44(GATE_8)
GATE_9T: Q17.4(G) U26.42(GATE_9)
GATE_10T: Q15.4(G) U26.40(GATE_10)
GATE_11T: Q15.2(G) U26.38(GATE_11)
MISO_1_: U26.29(SDO) ; port MISO_1
MOSI_1_: U26.28(SDI) ; port MOSI_1
nCS_TOPSTACK_: U26.30(~{CS}) ; port nCS_TOPSTACK
RS_EMB1428_: U26.35(RESET) ; port RS_EMB1428
SCLK_1_: U26.27(SCL_C) ; port SCLK_1
VREF_TOP_: port VREF_TOP, sheet TOP_Converter/VREF_TOP
NetC136_1: Q15.5(D) Q15.6(D) Q15.7(D) Q15.8(D) ; sheet TOP_Converter/PLUS_TOP
NetC209_2: C209.2 C_Vstack2.2 D2.4 D14.2(A) R29.1 U26.48(VSTACK)
NetC_Vstack2_1: C_Vstack2.1 D2.2 D14.1(K) U26.45(VDD_CP)
NetCEXT3_1: CEXT3.1 D2.3
NetCEXT3_2: CEXT3.2 U26.47(CEXT1)
NetCEXT4_1: CEXT4.1 D2.5 D2.6
NetCEXT4_2: CEXT4.2 U26.46(CEXT2)
NetD5_3: Q14.7(D) Q14.8(D) ; port TAP7
NetF2_1: Q16.7(D) Q16.8(D) ; port TAP6
NetF3_1: Q18.7(D) Q18.8(D) ; port TAP5
NetF4_1: Q19.7(D) Q19.8(D) ; port TAP4
NetF5_1: Q20.7(D) Q20.8(D) ; port TAP3
NetF6_2: Q21.7(D) Q21.8(D) ; port TAP2
NetF7_1: Q22.7(D) Q22.8(D) ; port TAP1
NetF8_2: Q23.7(D) Q23.8(D) ; port TAP0
NetQ14_1: Q14.1(S) Q14.3(S) U26.3(SOURCE_7)
NetQ14_2: Q14.2(G) Q14.4(G) U26.4(GATE_7)
NetQ14_5: Q14.5(D) Q14.6(D) Q15.1(S) Q17.5(D) Q17.6(D) Q18.5(D) Q18.6(D) Q20.5(D) Q20.6(D) Q22.5(D) Q22.6(D) U26.37(SOURCE_11)
NetQ15_3: Q15.3(S) Q16.5(D) Q16.6(D) Q17.7(D) Q17.8(D) Q19.5(D) Q19.6(D) Q21.5(D) Q21.6(D) Q23.5(D) Q23.6(D) U26.39(SOURCE_10)
NetQ16_1: Q16.1(S) Q16.3(S) U26.5(SOURCE_6)
NetQ16_2: Q16.2(G) Q16.4(G) U26.6(GATE_6)
NetQ18_1: Q18.1(S) Q18.3(S) U26.7(SOURCE_5)
NetQ18_2: Q18.2(G) Q18.4(G) U26.8(GATE_5)
NetQ19_1: Q19.1(S) Q19.3(S) U26.9(SOURCE_4)
NetQ19_2: Q19.2(G) Q19.4(G) U26.10(GATE_4)
NetQ20_1: Q20.1(S) Q20.3(S) U26.11(SOURCE_3)
NetQ20_2: Q20.2(G) Q20.4(G) U26.12(GATE_3)
NetQ21_1: Q21.1(S) Q21.3(S) U26.14(SOURCE_2)
NetQ21_2: Q21.2(G) Q21.4(G) U26.15(GATE_2)
NetQ22_1: Q22.1(S) Q22.3(S) U26.16(SOURCE_1)
NetQ22_2: Q22.2(G) Q22.4(G) U26.17(GATE_1)
NetQ23_1: Q23.1(S) Q23.3(S) U26.18(SOURCE_0)
NetQ23_2: Q23.2(G) Q23.4(G) U26.19(GATE_0)
NetU26_20: U26.20(FAULT_2) ; sheet TOP_Converter/FAULT_2
NetU26_21: U26.21(FAULT_1) ; sheet TOP_Converter/FAULT_1
NetU26_22: U26.22(FAULT_0) ; sheet TOP_Converter/FAULT_0

Not connected (* = marked no-connect by the designer): D2 1

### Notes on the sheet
- Odd
- Even
- TI Information - Selective Disclosure

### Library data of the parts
C118-C120 = C1608X7R1C104K: CAP, CERM, 0.1uF, 16V, +/-10%, X7R, 0603; Manufacturer: TDK; Cap_Case: 0603; ESR_Ohm: 0.017; Polarized: N; TaMax_C: 125; TaMin_C: -55; Tolerance_%: 10; VDC_V: 16; Cap_F: 0.0000001; CompType: Capacitor; Value1: 0.017 ohm; U/M: EA; ValueDisplayed: 0.1µF
C209 = C3216X7R2A105M: CAP, CERM, 1uF, 100V, +/-20%, C Series, 1206; Manufacturer: TDK; Cap_Case: 1206; ESR_Ohm: 0.006; IRMS_A: 4.5; Polarized: N; TaMax_C: 125; TaMin_C: -55; Tolerance_%: 20; VDC_V: 100; Cap_F: 0.000001; CompType: Capacitor; Value1: 0.006 ohm; U/M: EA; ValueDisplayed: 1µF
C210 = EMK212BJ475KG-T: CAP, CERM, 4.7uF, 16V, +/-10%, X5R, 0805; Manufacturer: Taiyo Yuden; Cap_Case: 0805; Polarized: N; TaMax_C: 85; TaMin_C: -55; Tolerance_%: 10; VDC_V: 16; Cap_F: 0.0000047; CompType: Capacitor; U/M: EA; ValueDisplayed: 4.7µF
C_Vstack2 CEXT3 CEXT4 = HMK212B7104KG-T: CAP, CERM, 0.1uF, 100V, +/-10%, X7R, 0805; Manufacturer: Taiyo Yuden; Cap_Case: 0805; Polarized: N; TaMax_C: 125; TaMin_C: -55; Tolerance_%: 10; VDC_V: 100; Cap_F: 0.0000001; CompType: Capacitor; U/M: EA
D2 = BAV99S: H-S switching diode; Manufacturer: NXP Semiconductors; SymbolVersion: use current date i.e. 2008-05-20; SymbolCreator: Use LDAP id
D14 = BAT41ZFILM: Diode, Schottky, 100V, 0.2A, SOD-123; Manufacturer: ST Microelectronics; Vf_V: 1; Io_A: 0.2; Vr_V: 100; TJMax_C: 150; Value: 1V; U/M: EA
Q14 Q16 Q18-Q23 = SI7938 VER1: DUAL N CHANNEL MOSFET, 40V, 60A; Manufacturer: Vishay; CompType: DUAL N-Chan MOSFET; Power_W: 3.5W; Res_Ohm: 7mOhm
Q15 Q17 = SI7938: DUAL N CHANNEL MOSFET, 40V, 60A; Manufacturer: Vishay; CompType: DUAL N-Chan MOSFET 30V Rdson < 17mOhm; Power_W: 3.5W; Res_Ohm: 7mOhm
R29 = CRCW0603499RFKEA: RES, 499 ohm, 1%, 0.1W, 0603; Manufacturer: Vishay-Dale; CompType: Resistor; Tolerance_%: 1; VDC_V: 75; Power_W: 0.1; Value_Code: 499R; EIA_Code: E96; TempCo: 100 ppm/C; U/M: EA
U26 = EMB1428QSQ: 12 channel Gate Controller; Manufacturer: National Semiconductor

## Sheet TOP_ACB_Converter.SchDoc: Top Tigon (PWM controller)
size B; Date: Not shown in title block; ApprovedBy: Not shown in title block; CheckedBy: Not shown in title block; Author: Not shown in title block; CompanyName: Not shown in title block; DrawnBy: Not shown in title block; Engineer: Not shown in title block; Organization: Not shown in title block; Address1: Not shown in title block; Address2: Not shown in title block; Address3: Not shown in title block; Address4: Not shown in title block; DocumentNumber: 8; Revision: Use project parameter SCH_Rev; SheetNumber: 9; SheetTotal: 14; PageSetup: Record=PageOptions|CenterHorizontal=True|CenterVertical=True|PrintScale=1.09|XCorrection=1.00|YCorrection=1.00|PrintKind=0|BorderSize=5000000|LeftOffset=0|BottomOffset=0|Orientation=2|PaperLength=1000|PaperWidth=1000|Scale=100|PaperSource=15|PrintQuality=600|MediaType=1|DitherType=10|PaperKind=11x17|PrintScaleMode=1
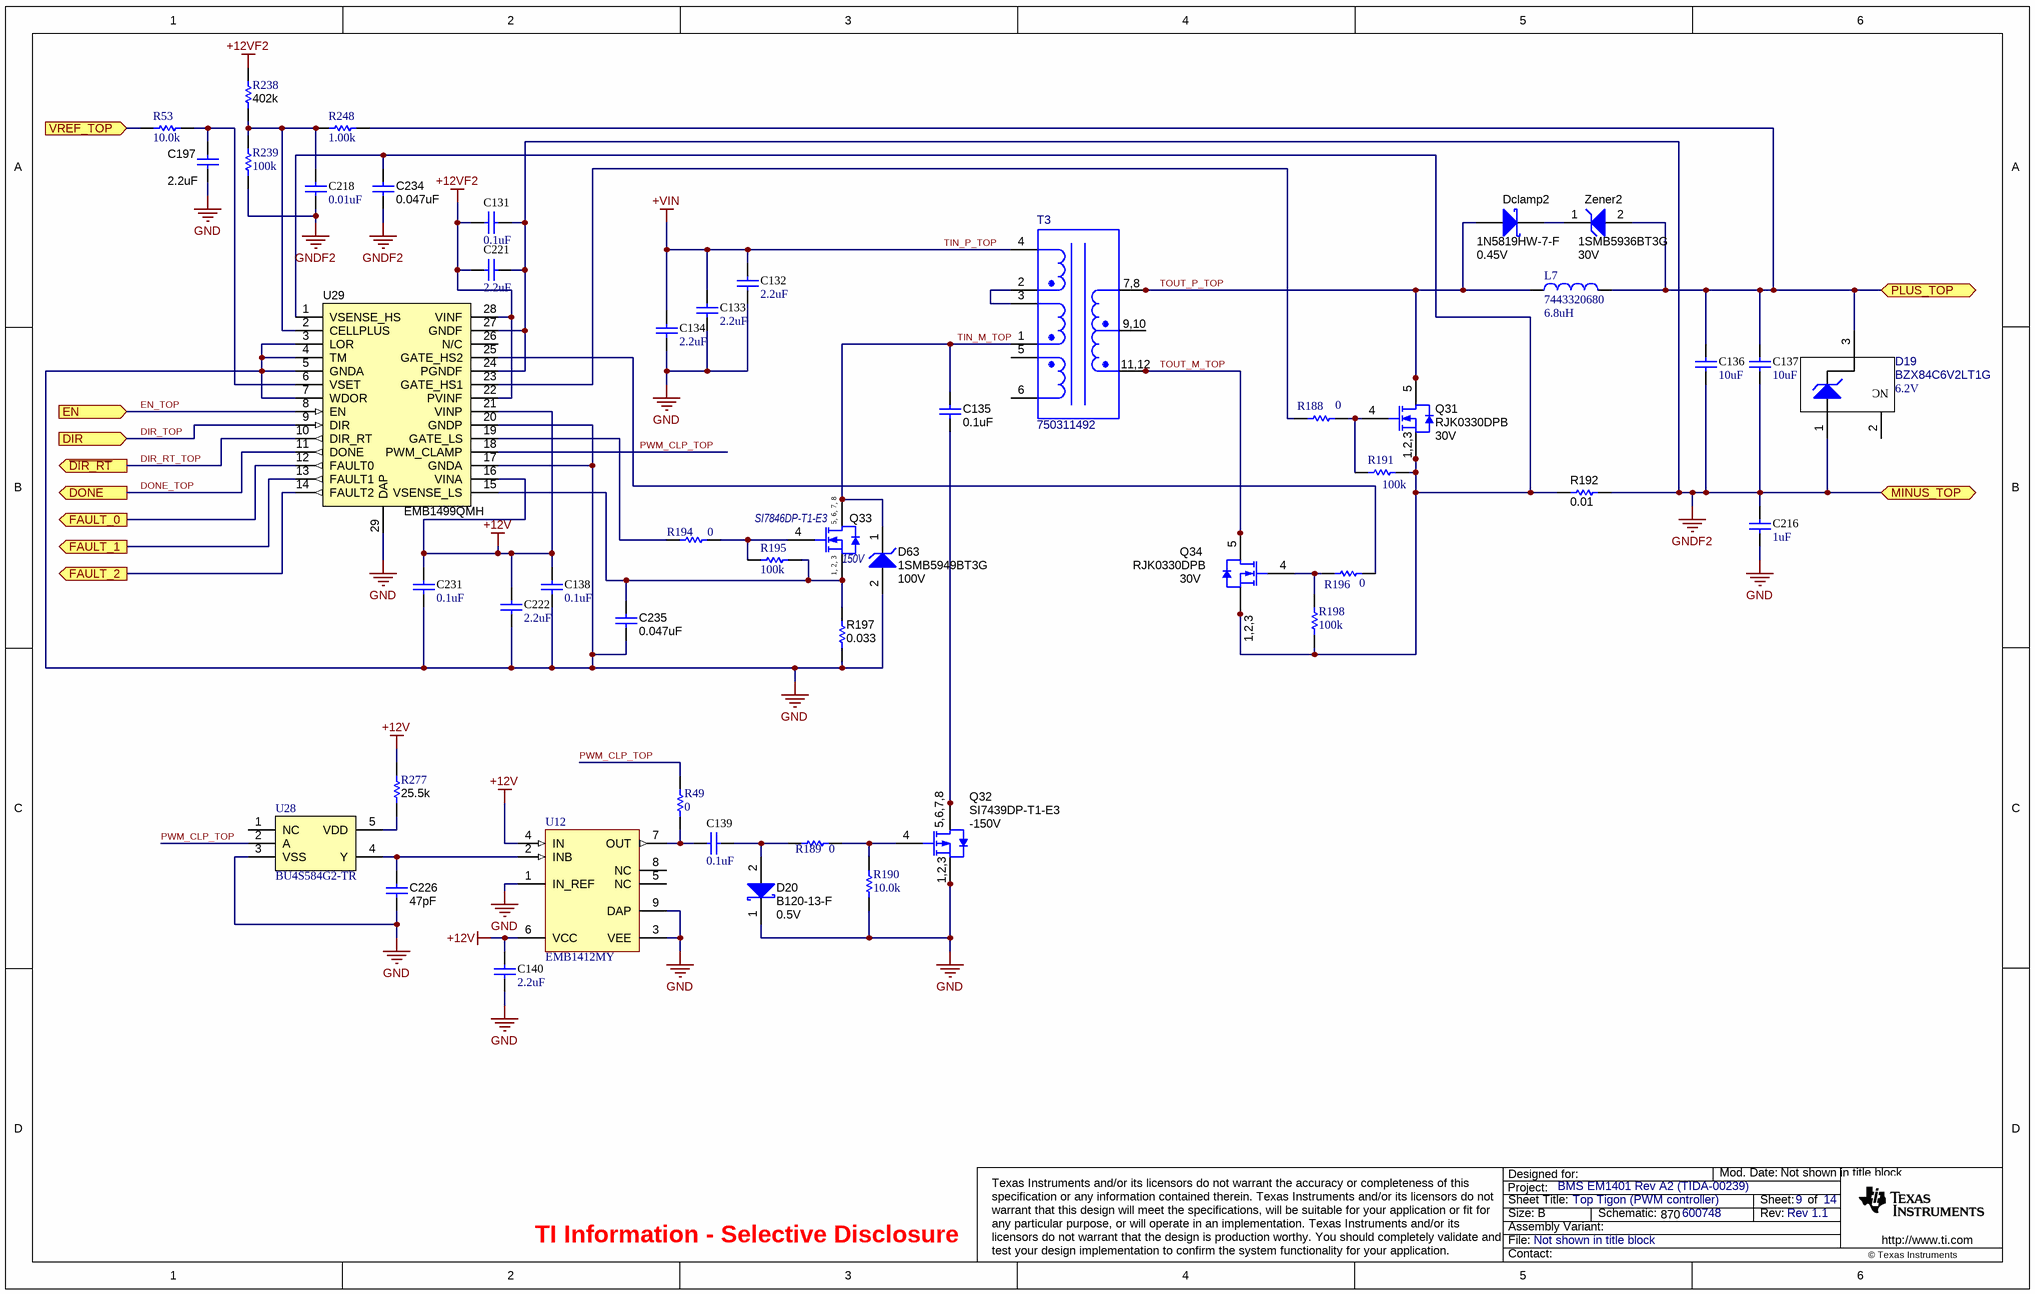
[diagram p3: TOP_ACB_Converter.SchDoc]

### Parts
C131  value 0.1uF  [0603L]  (hidden comment: C1608X7R1C104K)
C132  value 2.2uF  [1210L]  (hidden comment: GRM32ER72A225KA35L)
C133  value 2.2uF  [1210L]  (hidden comment: GRM32ER72A225KA35L)
C134  value 2.2uF  [1210L]  (hidden comment: GRM32ER72A225KA35L)
C135  value 0.1uF  [1206L]  (hidden comment: 12061C104KAT2A)
C136  value 10uF  [1206L]  (hidden comment: GRM319R61A106KE19D)
C137  value 10uF  [1206L]  (hidden comment: GRM319R61A106KE19D)
C138  value 0.1uF  [0603L]  (hidden comment: C1608X7R1C104K)
C139  value 0.1uF  [0603L]  (hidden comment: C1608X7R1C104K)
C140  value 2.2uF  [0805_HV]  (hidden comment: C0805C225K4RACTU)
C197  value 2.2uF  [0603L]  (hidden comment: C1608X5R0J225M)
C216  value 1uF  [1210L]  (hidden comment: GRM32ER72A105KA01L)
C218  value 0.01uF  [0603L]  (hidden comment: GRM188R71C103KA01D)
C221  value 2.2uF  [0805_HV]  (hidden comment: C0805C225K4RACTU)
C222  value 2.2uF  [0805_HV]  (hidden comment: C0805C225K4RACTU)
C226  value 47pF  [0603L]  (hidden comment: 06035A470JAT2A)
C231  value 0.1uF  [0603L]  (hidden comment: C1608X7R1C104K)
C234  value 0.047uF  [0603L]  (hidden comment: C1608X7R1E473K)
C235  value 0.047uF  [0603L]  (hidden comment: C1608X7R1E473K)
D19  BZX84C6V2LT1G  value 6.2V  [MF03A_L]
D20  B120-13-F  value 0.5V  [SMA]
D63  1SMB5949BT3G  value 100V  [SMB]
Dclamp2  1N5819HW-7-F  value 0.45V  [SOD-123]
L7  7443320680  Ind_H: 6.8uH  [Wurth 7443320680]
Q31  RJK0330DPB  value 30V  [LFPAK]
Q32  SI7439DP-T1-E3  value -150V  [PowerPAK_SO-8]
Q33  SI7846DP-T1-E3  value 150V  [PowerPAK_SO-8]
Q34  RJK0330DPB  value 30V  [LFPAK]
R49  value 0  [0603L]  (hidden comment: CRCW06030000Z0EA)
R53  value 10.0k  [0603L]  (hidden comment: RT0603BRD0710KL)
R188  value 0  [0603L]  (hidden comment: CRCW06030000Z0EA)
R189  value 0  [0603L]  (hidden comment: CRCW06030000Z0EA)
R190  value 10.0k  [0603L]  (hidden comment: RT0603BRD0710KL)
R191  value 100k  [0603L]  (hidden comment: CRCW0603100KFKEA)
R192  value 0.01  [2010M]  (hidden comment: WSL2010R0100FEA18)
R194  value 0  [0603L]  (hidden comment: CRCW06030000Z0EA)
R195  value 100k  [0603L]  (hidden comment: CRCW0603100KFKEA)
R196  value 0  [0603L]  (hidden comment: CRCW06030000Z0EA)
R197  value 0.033  [1812]  (hidden comment: ERJ-L12KF33MU)
R198  value 100k  [0603L]  (hidden comment: CRCW0603100KFKEA)
R238  value 402k  [0603L]  (hidden comment: RC0603FR-07402KL)
R239  value 100k  [0603L]  (hidden comment: CRCW0603100KFKEA)
R248  value 1.00k  [0603L]  (hidden comment: CRCW06031K00FKEA)
R277  value 25.5k  [0603L]  (hidden comment: CRCW060325K5FKEA)
T3  750311492  [WE EFD20-SMD Transformer]
U12  EMB1412MY  [MUY08A_N]
U28  BU4S584G2-TR  [MF05A_M]
U29  EMB1499QMH  [MXA28A_M]
Zener2  1SMB5936BT3G  value 30V  [SMB]

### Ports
DIR (in), DONE (out), EN (in), FAULT_0 (out), FAULT_1 (out), FAULT_2 (out), MINUS_TOP (bidir), PLUS_TOP (bidir), VREF_TOP (in), ~{DIR_RT} (out)

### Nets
+12V: C138.2 C140.1 C222.1 C231.2 R277.2 U12.4(IN) U12.6(VCC) U29.16(VINA) U29.21(VINP)
+12VF2: C131.1 C221.1 R238.2 U29.22(PVINF) U29.28(VINF)
+VIN: C132.1 C133.1 C134.1 T3.4  [also labelled TIN_P_TOP]  [project net TIN_P_BOT]
GND: C132.2 C133.2 C134.2 C138.1 C140.2 C197.2 C216.2 C222.2 C226.2 C231.1 C235.1 D20.1(K) D63.2(A) Q32.1(S) Q32.2(S) Q32.3(S) R190.2 R197.1 U12.1(IN_REF) U12.3(VEE) U12.9(DAP) U28.3(VSS) U29.3(LOR) U29.4(TM) U29.5(GNDA) U29.7(WDOR) U29.17(GNDA) U29.20(GNDP) U29.29(DAP)  [project net BAT0]
GNDF2: C131.2 C136.2 C137.2 C216.1 C218.2 C221.2 C234.1 D19.1(A) R192.2 R239.2 U29.24(PGNDF) U29.27(GNDF) ; port MINUS_TOP
DIR_RT_TOP: U29.10(DIR_RT) ; port ~{DIR_RT}
DIR_TOP: U29.9(DIR) ; port DIR
DONE_TOP: U29.11(DONE) ; port DONE
EN_TOP: U29.8(EN) ; port EN
PWM_CLP_TOP: R49.1 U28.2(A) U29.18(PWM_CLAMP)
TIN_M_TOP: C135.1 D63.1(K) Q33.5(D) Q33.6(D) Q33.7(D) Q33.8(D) T3.1
TOUT_M_TOP: Q34.5(D) Q34.6(D) T3.11 T3.12
TOUT_P_TOP: Dclamp2.2(A) L7.1 Q31.5(D) Q31.6(D) T3.7 T3.8
VREF_TOP_: R53.2 ; port VREF_TOP
NetC135_2: C135.2 Q32.5(D) Q32.6(D) Q32.7(D) Q32.8(D) Q32.9(D)
NetC136_1: C136.1 C137.1 D19.3(K) L7.2 R248.1 Zener2.2(A) ; port PLUS_TOP
NetC139_1: C139.1 D20.2(A) R189.2
NetC139_2: C139.2 R49.2 U12.7(OUT)
NetC197_1: C197.1 R53.1 U29.6(VSET)
NetC218_1: C218.1 R238.1 R239.1 R248.2 U29.2(CELLPLUS)
NetC226_1: C226.1 U12.2(INB) U28.4(Y)
NetC234_2: C234.2 Q31.1(S) Q31.2(S) Q31.3(S) Q34.1(S) Q34.2(S) Q34.3(S) R191.1 R192.1 R198.2 U29.1(VSENSE_HS)
NetC235_2: C235.2 Q33.1(S) Q33.2(S) Q33.3(S) R195.1 R197.2 U29.15(VSENSE_LS)
NetDclamp2_1: Dclamp2.1(K) Zener2.1(K)
NetQ31_4: Q31.4(G) R188.1 R191.2
NetQ32_4: Q32.4(G) R189.1 R190.1
NetQ33_4: Q33.4(G) R194.1 R195.2
NetQ34_4: Q34.4(G) R196.2 R198.1
NetR188_2: R188.2 U29.23(GATE_HS1)
NetR194_2: R194.2 U29.19(GATE_LS)
NetR196_1: R196.1 U29.25(GATE_HS2)
NetR277_1: R277.1 U28.5(VDD)
NetT3_2: T3.2 T3.3
NetT3_9: T3.9 T3.10
NetU26_20: U29.14(FAULT2) ; port FAULT_2
NetU26_21: U29.13(FAULT1) ; port FAULT_1
NetU26_22: U29.12(FAULT0) ; port FAULT_0

Not connected (* = marked no-connect by the designer): D19 2(NC); T3 5 6; U12 5(NC) 8(NC); U28 1(NC); U29 26(N/C)

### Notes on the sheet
- TI Information - Selective Disclosure

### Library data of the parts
C131 C138 C139 C231 = C1608X7R1C104K: as C118 on sheet TOP Half Stack
C132-C134 = GRM32ER72A225KA35L: CAP, CERM, 2.2uF, 100V, +/-10%, X7R, 1210; Manufacturer: MuRata; Cap_Case: 1210; ESR_Ohm: 0.007; IRMS_A: 4.4; Polarized: N; TaMax_C: 125; TaMin_C: -55; Tolerance_%: 10; VDC_V: 100; Cap_F: 0.0000022; CompType: Capacitor; Value1: 0.007 ohm; U/M: EA; ValueDisplayed: 2.2µF
C135 = 12061C104KAT2A: CAP, CERM, 0.1uF, 100V, +/-10%, X7R, 1206; Manufacturer: AVX; Cap_Case: 1206; ESR_Ohm: 0.037; Polarized: N; TaMax_C: 125; TaMin_C: -55; Tolerance_%: 10; VDC_V: 100; Cap_F: 0.0000001; CompType: Capacitor; Value1: 0.037 ohm; U/M: EA; ValueDisplayed: 0.1µF
C136 C137 = GRM319R61A106KE19D: CAP, CERM, 10uF, 10V, +/-10%, X5R, 1206; Manufacturer: MuRata; Cap_Case: 1206; ESR_Ohm: 0.004; Polarized: N; TaMax_C: 85; TaMin_C: -55; Tolerance_%: 10; Cap_F: 0.00001; CompType: Capacitor; Value1: 0.004 ohm; U/M: EA; ValueDisplayed: 10µF
C140 C221 C222 = C0805C225K4RACTU: CAP, CERM, 2.2uF, 16V, +/-10%, X7R, 0805; Manufacturer: Kemet; Cap_Case: 0805; ESR_Ohm: 0.008; IRMS_A: 15.55; Polarized: N; TaMax_C: 125; TaMin_C: -55; Tolerance_%: 10; VDC_V: 16; Cap_F: 0.0000022; CompType: Capacitor; Value1: 0.008 ohm; U/M: EA; ValueDisplayed: 2.2µF
C197 = C1608X5R0J225M: CAP, CERM, 2.2uF, 6.3V, +/-20%, X5R, 0603; Manufacturer: TDK; Cap_Case: 0603; ESR_Ohm: 0.004; Polarized: N; TaMax_C: 85; TaMin_C: -55; Tolerance_%: 20; VDC_V: 6.3; Cap_F: 0.0000022; CompType: Capacitor; Value1: 0.004 ohm; U/M: EA; ValueDisplayed: 2.2µF
C216 = GRM32ER72A105KA01L: CAP, CERM, 1uF, 100V, +/-10%, X7R, 1210; Manufacturer: MuRata; Cap_Case: 1210; Polarized: N; TaMax_C: 125; TaMin_C: -55; Tolerance_%: 10; VDC_V: 100; Cap_F: 0.000001; CompType: Capacitor; U/M: EA; ValueDisplayed: 1µF
C218 = GRM188R71C103KA01D: CAP, CERM, 0.01uF, 16V, +/-10%, X7R, 0603; Manufacturer: MuRata; Cap_Case: 0603; Polarized: N; TaMax_C: 125; TaMin_C: -55; Tolerance_%: 10; VDC_V: 16; Cap_F: 0.00000001; CompType: Capacitor; U/M: EA; ValueDisplayed: 0.01µF
C226 = 06035A470JAT2A: CAP, CERM, 47pF, 50V, +/-5%, C0G/NP0, 0603; Manufacturer: AVX; Cap_Case: 0603; ESR_Ohm: 0.174; Polarized: N; TaMax_C: 125; TaMin_C: -55; Tolerance_%: 5; VDC_V: 50; Cap_F: 0.000000000047; CompType: Capacitor; Value1: 0.174 ohm; U/M: EA
C234 C235 = C1608X7R1E473K: CAP, CERM, 0.047uF, 25V, +/-10%, X7R, 0603; Manufacturer: TDK; Cap_Case: 0603; ESR_Ohm: 0.0234; Polarized: N; TaMax_C: 125; TaMin_C: -55; Tolerance_%: 10; VDC_V: 25; Cap_F: 0.000000047; CompType: Capacitor; Value1: 0.0234 ohm; U/M: EA; ValueDisplayed: 0.047µF
D19 = BZX84C6V2LT1G: SMT Zener Diode; Manufacturer: ON Semiconductor; Power_W: 0.225; Vz: 6.2; Value1: 0.225V; RJA_CperW: 556
D20 = B120-13-F: Diode, Schottky, 20V, 1A, SMA; Manufacturer: Diodes Inc.; RJC_CperW: 20; Vf_V: 0.5; Io_A: 1; TJMax_C: 150; U/M: EA
D63 = 1SMB5949BT3G: Diode, Zener, 100V, 550mW, SMB; Manufacturer: ON Semiconductor; U/M: EA; Power_W: 0.55; Vz: 100; Value1: 0.55W; RJA_CperW: 226
Dclamp2 = 1N5819HW-7-F: Diode, Schottky, 40V, 1A, SOD-123; Manufacturer: Diodes Inc.; Vf_V: 0.45; Io_A: 1; Vr_V: 40; TJMax_C: 125; U/M: EA
L7 = 7443320680: Wurth 6.8uH Power Inductor; Manufacturer: Wurth Elektronik; DCR_Ohm: 8.98; Value1: 13A
Q31 Q34 = RJK0330DPB: 45A, 27nC, rDS(on) @ 4.5V =0.0028 ohm; Manufacturer: Renesas; CompType: MOSFET; ChType: N; VdsMax_V: 30; Rdson45_Ohm: 0.0028; QgTyp_nC: 27; Vgs_V: 20; IdsMax_A: 45
Q32 = SI7439DP-T1-E3: MOSFET, P-CH, -150V, -3A, PowerPAK SO-8; Manufacturer: Vishay-Siliconix; ChType: P; VdsMax_V: -150; Value1: ? ohm; Value2: 88 nC; QgTyp_nC: 88; Vgs_V: -20; IdsMax_A: -3; U/M: EA
Q33 = BSC014N03LS G: 100A, 47nC, rDS(on) @ 4.5V =0.0021 Ohm; Manufacturer: Vishay/Siliconix; DesignatorOriginal: Q1-tw; A_Properties: MOSFET N-CH 150V 4A PPAK 8SOIC; Type: N-CH FET; Value1: 50mOhm; Value2: 30nC
R49 R188 R189 R194 R196 = CRCW06030000Z0EA: as R92 on sheet Top_Level
R53 R190 = RT0603BRD0710KL: RES, 10.0k ohm, 0.1%, 0.1W, 0603; Manufacturer: Yageo America; CompType: Resistor; Tolerance_%: 0.1; VDC_V: 75; Res_Ohm: 10000; Value_Code: 10k0; EIA_Code: E192; TempCo: 25 ppm/C; U/M: EA
R191 R195 R198 R239 = CRCW0603100kFKEA: as R167 on sheet Engine
R192 = WSL2010R0100FEA18: RES, 0.01 ohm, 1%, 1W, 2010; Manufacturer: Vishay-Dale; CompType: Resistor; Tolerance_%: 1; Value_Code: R010; EIA_Code: E96; TempCo: 75 ppm/C; U/M: EA
R197 = ERJ-L12KF33MU: RES, 0.033 ohm, 1%, 0.5W, 1812; Manufacturer: Panasonic; CompType: Resistor; Tolerance_%: 1; Power_W: 0.5; Value_Code: R033; EIA_Code: E96; TempCo: 300 ppm/C; U/M: EA
R238 = RC0603FR-07402KL: RES, 402k ohm, 1%, 0.1W, 0603; Manufacturer: Yageo America; CompType: Resistor; Tolerance_%: 1; VDC_V: 150; Power_W: 0.1; Res_ohm: 402000; EIA_Code: E96; U/M: EA; TempCo: 200 ppm/C
R248 = CRCW06031k00FKEA: RES, 1.00k ohm, 1%, 0.1W, 0603; Manufacturer: Vishay-Dale; CompType: Resistor; Tolerance_%: 1; VDC_V: 75; Power_W: 0.1; Res_Ohm: 1000; Value_Code: 1k00; EIA_Code: E96; TempCo: 100 ppm/C; U/M: EA
R277 = CRCW060325K5FKEA: RES, 25.5k ohm, 1%, 0.1W, 0603; Manufacturer: Vishay-Dale; CompType: Resistor; Tolerance_%: 1; VDC_V: 75; Power_W: 0.1; Res_Ohm: 25500; Value_Code: 25k5; EIA_Code: E96; TempCo: 100 ppm/C; U/M: EA
T3 = EFD20-SMD: Forward Transformer; Manufacturer: Wurth Elektronik; SymbolVersion: use current date i.e. 2008-05-20; SymbolCreator: Use LDAP id
U12 = EMB1412MY: Dual 5A Compound Gate Driver; Manufacturer: National Semiconductor; CompType: Switcher; PowerWise: N
U28 = BU4S584G2-TR: IC INVERTER WITH SCHMITT TRIGGER SINGLE; Manufacturer: Rohm Semiconductor; Res_Ohm: 200000; Value1: 3V-16V; Value2: 3.4mA Drive
U29 = EMB1499QMH: PWM Controller; Manufacturer: National Semiconductor; CompType: Used in BOM report; SymbolVersion: use current date i.e. 2008-05-20; SymbolCreator: Use LDAP id
Zener2 = 1SMB5936BT3G: Diode, Zener, 30V, 550mW, SMB; Manufacturer: ON Semiconductor; U/M: EA; Power_W: 0.55; Vz: 30; Value1: 0.55W; RJA_CperW: 226

## Sheet BOTTOM Half Stack.SchDoc: Bottom Half Stack
size B; Date: Not shown in title block; ApprovedBy: Not shown in title block; CheckedBy: Not shown in title block; Author: Not shown in title block; CompanyName: Not shown in title block; DrawnBy: Not shown in title block; Engineer: Not shown in title block; Organization: Not shown in title block; Address1: Not shown in title block; Address2: Not shown in title block; Address3: Not shown in title block; Address4: Not shown in title block; DocumentNumber: 5; Revision: Use project parameter SCH_Rev; SheetNumber: 6; SheetTotal: 14; PageSetup: Record=PageOptions|CenterHorizontal=True|CenterVertical=True|PrintScale=1.09|XCorrection=1.00|YCorrection=1.00|PrintKind=0|BorderSize=5000000|LeftOffset=0|BottomOffset=0|Orientation=2|PaperLength=1000|PaperWidth=1000|Scale=100|PaperSource=15|PrintQuality=600|MediaType=1|DitherType=10|PaperKind=11x17|PrintScaleMode=1
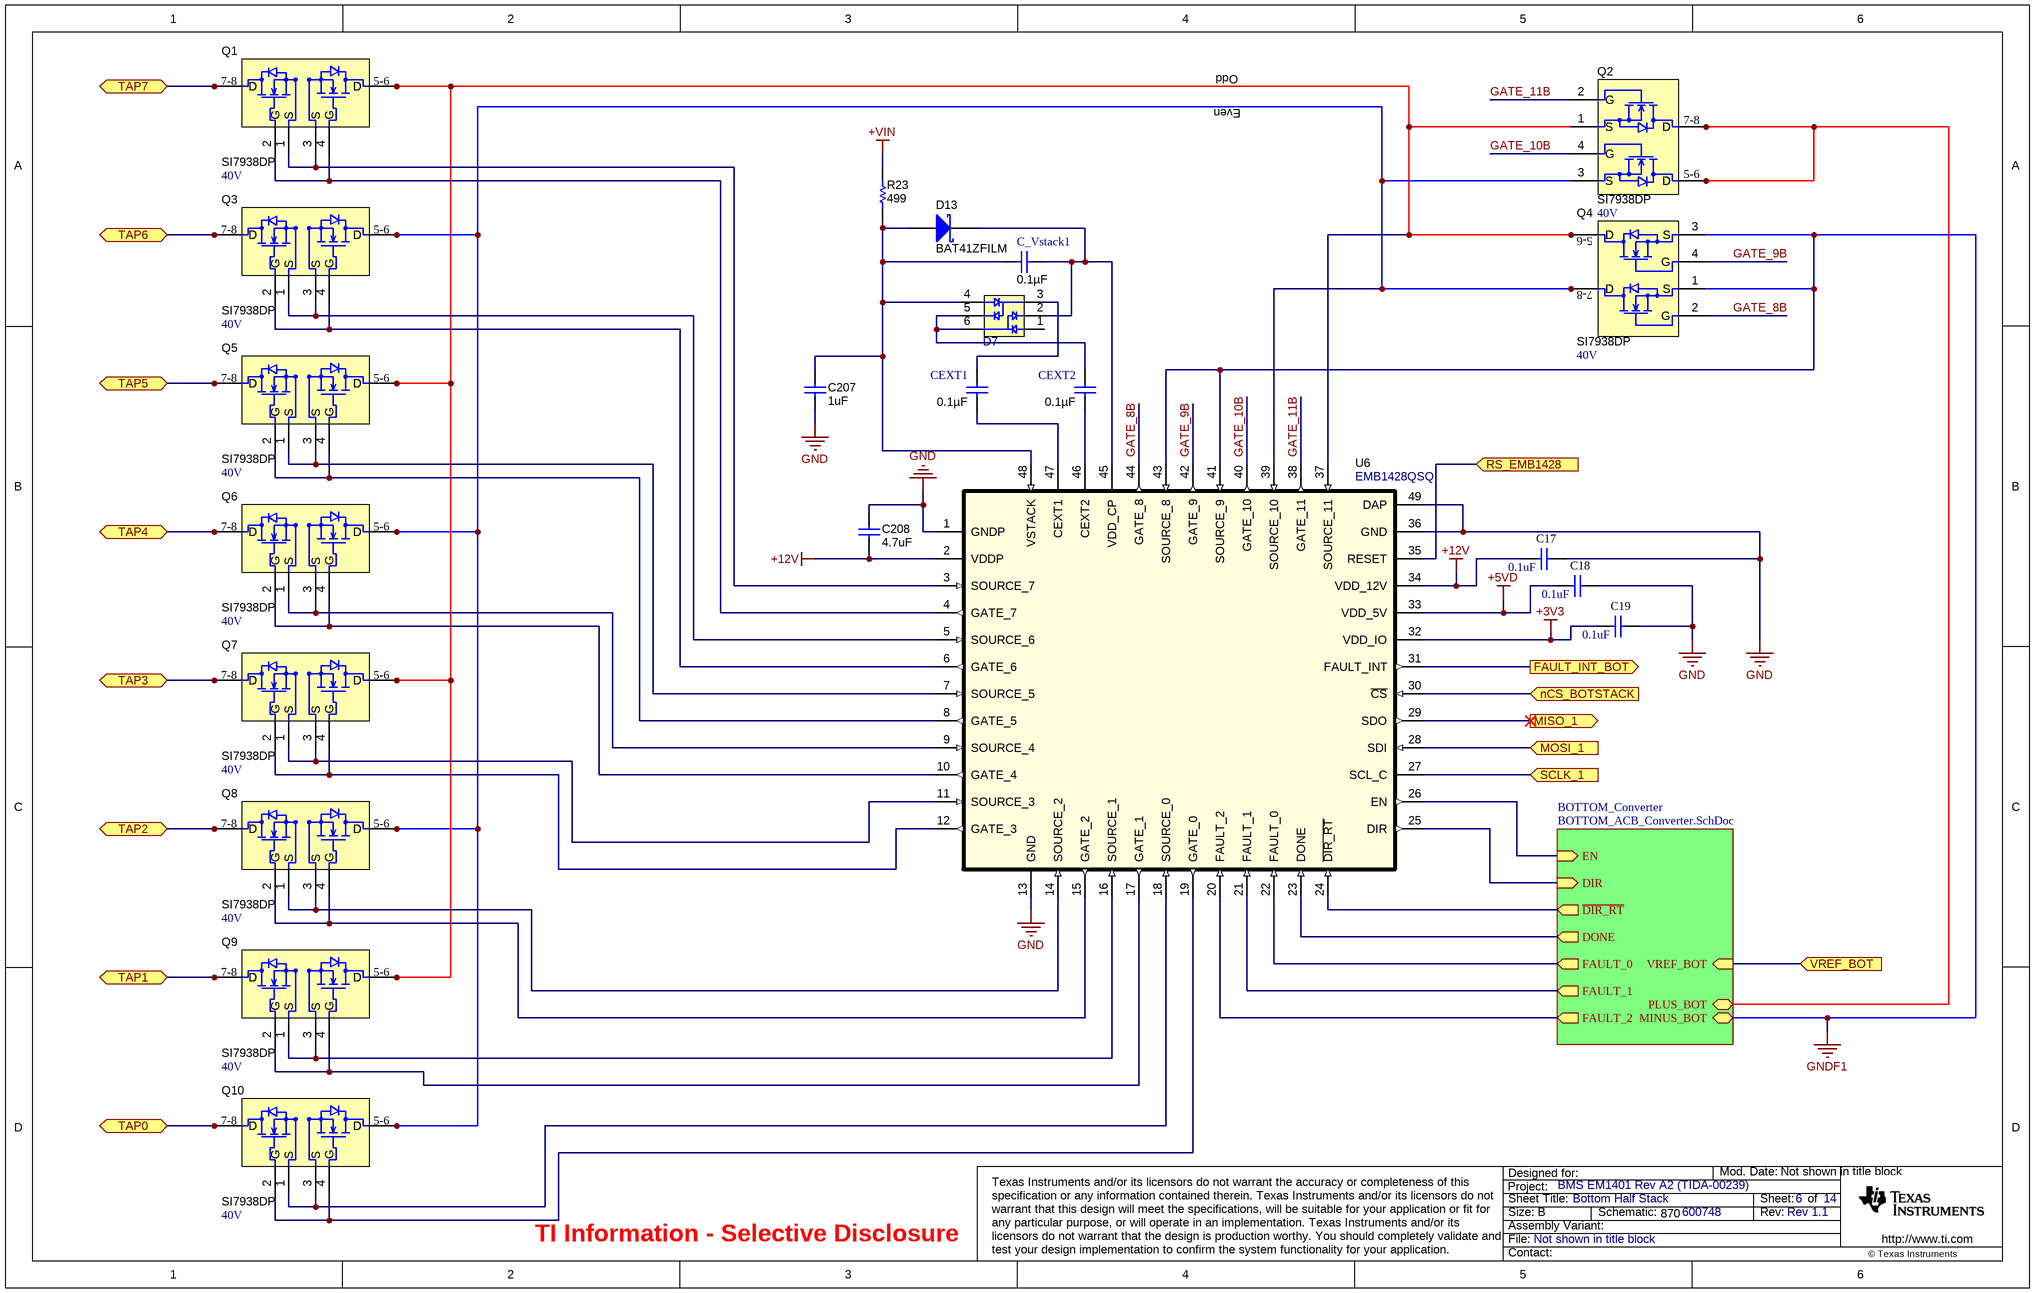
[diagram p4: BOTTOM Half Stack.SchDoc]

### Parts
C17  value 0.1uF  [0603L]  (hidden comment: C1608X7R1C104K)
C18  value 0.1uF  [0603L]  (hidden comment: C1608X7R1C104K)
C19  value 0.1uF  [0603L]  (hidden comment: C1608X7R1C104K)
C207  value 1uF  [1206L]  (hidden comment: C3216X7R2A105M)
C208  value 4.7uF  [0805_HV]  (hidden comment: EMK212BJ475KG-T)
C_Vstack1  ValueDisplayed: 0.1µF  [0805_HV]  (hidden comment: HMK212B7104KG-T)
CEXT1  ValueDisplayed: 0.1µF  [0805_HV]  (hidden comment: HMK212B7104KG-T)
CEXT2  ValueDisplayed: 0.1µF  [0805_HV]  (hidden comment: HMK212B7104KG-T)
D7  BAV99S  [SOT-363]  (value not drawn)
D13  BAT41ZFILM  [SOD-123]
Q1  SI7938DP  Value2: 40V  [POWERPAK SO-8 -Dual]
Q2  SI7938DP  value 40V  [POWERPAK SO-8 -Dual]
Q3  SI7938DP  Value2: 40V  [POWERPAK SO-8 -Dual]
Q4  SI7938DP  value 40V  [POWERPAK SO-8 -Dual]
Q5  SI7938DP  Value2: 40V  [POWERPAK SO-8 -Dual]
Q6  SI7938DP  Value2: 40V  [POWERPAK SO-8 -Dual]
Q7  SI7938DP  Value2: 40V  [POWERPAK SO-8 -Dual]
Q8  SI7938DP  Value2: 40V  [POWERPAK SO-8 -Dual]
Q9  SI7938DP  Value2: 40V  [POWERPAK SO-8 -Dual]
Q10  SI7938DP  Value2: 40V  [POWERPAK SO-8 -Dual]
R23  value 499  [0603L]  (hidden comment: CRCW0603499RFKEA)
U6  EMB1428QSQ  [sqa48a]

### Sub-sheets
BOTTOM_Converter = BOTTOM_ACB_Converter.SchDoc: FAULT_2 (out), FAULT_1 (out), FAULT_0 (out), DIR (in), ~{DIR_RT} (out), DONE (out), EN (in), MINUS_BOT (bidir), PLUS_BOT (bidir), VREF_BOT (in)

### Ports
FAULT_INT_BOT (out), MISO_1 (out), MOSI_1 (in), nCS_BOTSTACK (in), RS_EMB1428 (in), SCLK_1 (in), TAP0 (see 1[4C]), TAP1 (see 1[4C]), TAP2 (see 1[4B]), TAP3 (see 1[4B]), TAP4 (see 1[4B]), TAP5 (see 1[4B]), TAP6 (see 1[4B]), TAP7 (see 1[4B]), VREF_BOT (in)

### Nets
+3V3: C19.2 U6.32(VDD_IO)
+5VD: C18.2 U6.33(VDD_5V)
+12V: C17.2 C208.2 U6.2(VDDP) U6.34(VDD_12V)
+VIN: R23.2  [project net TIN_P_BOT]
GND: C17.1 C18.1 C19.1 C207.1 C208.1 U6.1(GNDP) U6.13(GND) U6.36(GND) U6.49(DAP)  [project net BAT0]
GNDF1: Q4.1(S) Q4.3(S) U6.41(SOURCE_9) U6.43(SOURCE_8) ; sheet BOTTOM_Converter/MINUS_BOT
DIR_BOT: U6.25(DIR) ; sheet BOTTOM_Converter/DIR
DIR_RT_BOT: U6.24(~{DIR_RT}) ; sheet BOTTOM_Converter/~{DIR_RT}
DONE_BOT: U6.23(DONE) ; sheet BOTTOM_Converter/DONE
EN_BOT: U6.26(EN) ; sheet BOTTOM_Converter/EN
FAULT_INT_BOT_: U6.31(FAULT_INT) ; port FAULT_INT_BOT
GATE_8B: Q4.2(G) U6.44(GATE_8)
GATE_9B: Q4.4(G) U6.42(GATE_9)
GATE_10B: Q2.4(G) U6.40(GATE_10)
GATE_11B: Q2.2(G) U6.38(GATE_11)
MISO_1_: U6.29(SDO) ; port MISO_1
MOSI_1_: U6.28(SDI) ; port MOSI_1
nCS_BOTSTACK_: U6.30(~{CS}) ; port nCS_BOTSTACK
RS_EMB1428_: U6.35(RESET) ; port RS_EMB1428
SCLK_1_: U6.27(SCL_C) ; port SCLK_1
VREF_BOT_: port VREF_BOT, sheet BOTTOM_Converter/VREF_BOT
NetC126_1: Q2.5(D) Q2.6(D) Q2.7(D) Q2.8(D) ; sheet BOTTOM_Converter/PLUS_BOT
NetC207_2: C207.2 C_Vstack1.2 D7.4 D13.2(A) R23.1 U6.48(VSTACK)
NetC_Vstack1_1: C_Vstack1.1 D7.2 D13.1(K) U6.45(VDD_CP)
NetCEXT1_1: CEXT1.1 D7.3
NetCEXT1_2: CEXT1.2 U6.47(CEXT1)
NetCEXT2_1: CEXT2.1 D7.5 D7.6
NetCEXT2_2: CEXT2.2 U6.46(CEXT2)
NetF8_2: Q1.7(D) Q1.8(D) ; port TAP7
NetF9_1: Q3.7(D) Q3.8(D) ; port TAP6
NetF10_1: Q5.7(D) Q5.8(D) ; port TAP5
NetF11_1: Q6.7(D) Q6.8(D) ; port TAP4
NetF12_1: Q7.7(D) Q7.8(D) ; port TAP3
NetF13_1: Q8.7(D) Q8.8(D) ; port TAP2
NetF14_1: Q9.7(D) Q9.8(D) ; port TAP1
NetF15_1: Q10.7(D) Q10.8(D) ; port TAP0
NetQ1_1: Q1.1(S) Q1.3(S) U6.3(SOURCE_7)
NetQ1_2: Q1.2(G) Q1.4(G) U6.4(GATE_7)
NetQ1_5: Q1.5(D) Q1.6(D) Q2.1(S) Q4.5(D) Q4.6(D) Q5.5(D) Q5.6(D) Q7.5(D) Q7.6(D) Q9.5(D) Q9.6(D) U6.37(SOURCE_11)
NetQ2_3: Q2.3(S) Q3.5(D) Q3.6(D) Q4.7(D) Q4.8(D) Q6.5(D) Q6.6(D) Q8.5(D) Q8.6(D) Q10.5(D) Q10.6(D) U6.39(SOURCE_10)
NetQ3_1: Q3.1(S) Q3.3(S) U6.5(SOURCE_6)
NetQ3_2: Q3.2(G) Q3.4(G) U6.6(GATE_6)
NetQ5_1: Q5.1(S) Q5.3(S) U6.7(SOURCE_5)
NetQ5_2: Q5.2(G) Q5.4(G) U6.8(GATE_5)
NetQ6_1: Q6.1(S) Q6.3(S) U6.9(SOURCE_4)
NetQ6_2: Q6.2(G) Q6.4(G) U6.10(GATE_4)
NetQ7_1: Q7.1(S) Q7.3(S) U6.11(SOURCE_3)
NetQ7_2: Q7.2(G) Q7.4(G) U6.12(GATE_3)
NetQ8_1: Q8.1(S) Q8.3(S) U6.14(SOURCE_2)
NetQ8_2: Q8.2(G) Q8.4(G) U6.15(GATE_2)
NetQ9_1: Q9.1(S) Q9.3(S) U6.16(SOURCE_1)
NetQ9_2: Q9.2(G) Q9.4(G) U6.17(GATE_1)
NetQ10_1: Q10.1(S) Q10.3(S) U6.18(SOURCE_0)
NetQ10_2: Q10.2(G) Q10.4(G) U6.19(GATE_0)
NetU6_20: U6.20(FAULT_2) ; sheet BOTTOM_Converter/FAULT_2
NetU6_21: U6.21(FAULT_1) ; sheet BOTTOM_Converter/FAULT_1
NetU6_22: U6.22(FAULT_0) ; sheet BOTTOM_Converter/FAULT_0

Not connected (* = marked no-connect by the designer): D7 1

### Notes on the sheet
- Odd
- Even
- TI Information - Selective Disclosure

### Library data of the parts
C17-C19 = C1608X7R1C104K: as C118 on sheet TOP Half Stack
C207 = C3216X7R2A105M: as C209 on sheet TOP Half Stack
C208 = EMK212BJ475KG-T: as C210 on sheet TOP Half Stack
C_Vstack1 CEXT1 CEXT2 = HMK212B7104KG-T: as C_Vstack2 on sheet TOP Half Stack
D7 = BAV99S: as D2 on sheet TOP Half Stack
D13 = BAT41ZFILM: as D14 on sheet TOP Half Stack
Q1 Q3 Q5-Q10 = SI7938 VER1: as Q14 on sheet TOP Half Stack
Q2 Q4 = SI7938: as Q15 on sheet TOP Half Stack
R23 = CRCW0603499RFKEA: as R29 on sheet TOP Half Stack
U6 = EMB1428QSQ: as U26 on sheet TOP Half Stack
